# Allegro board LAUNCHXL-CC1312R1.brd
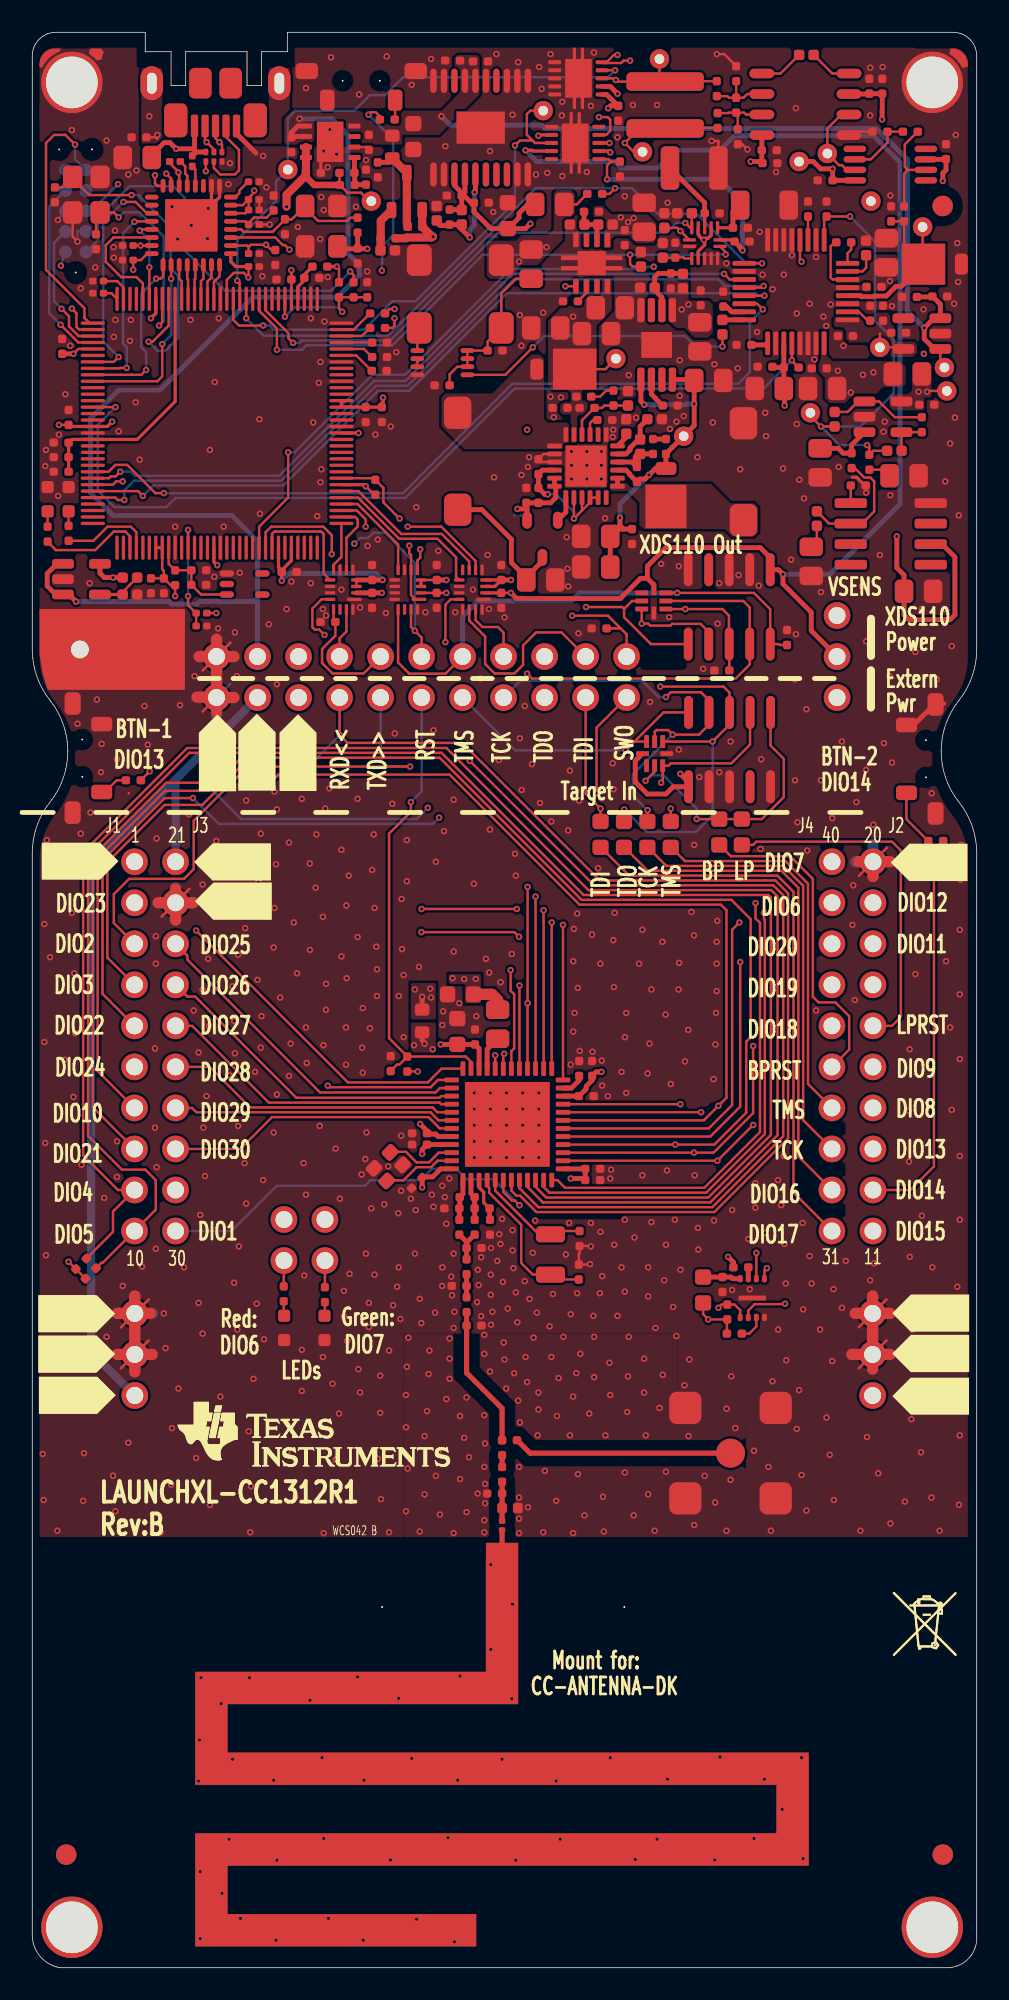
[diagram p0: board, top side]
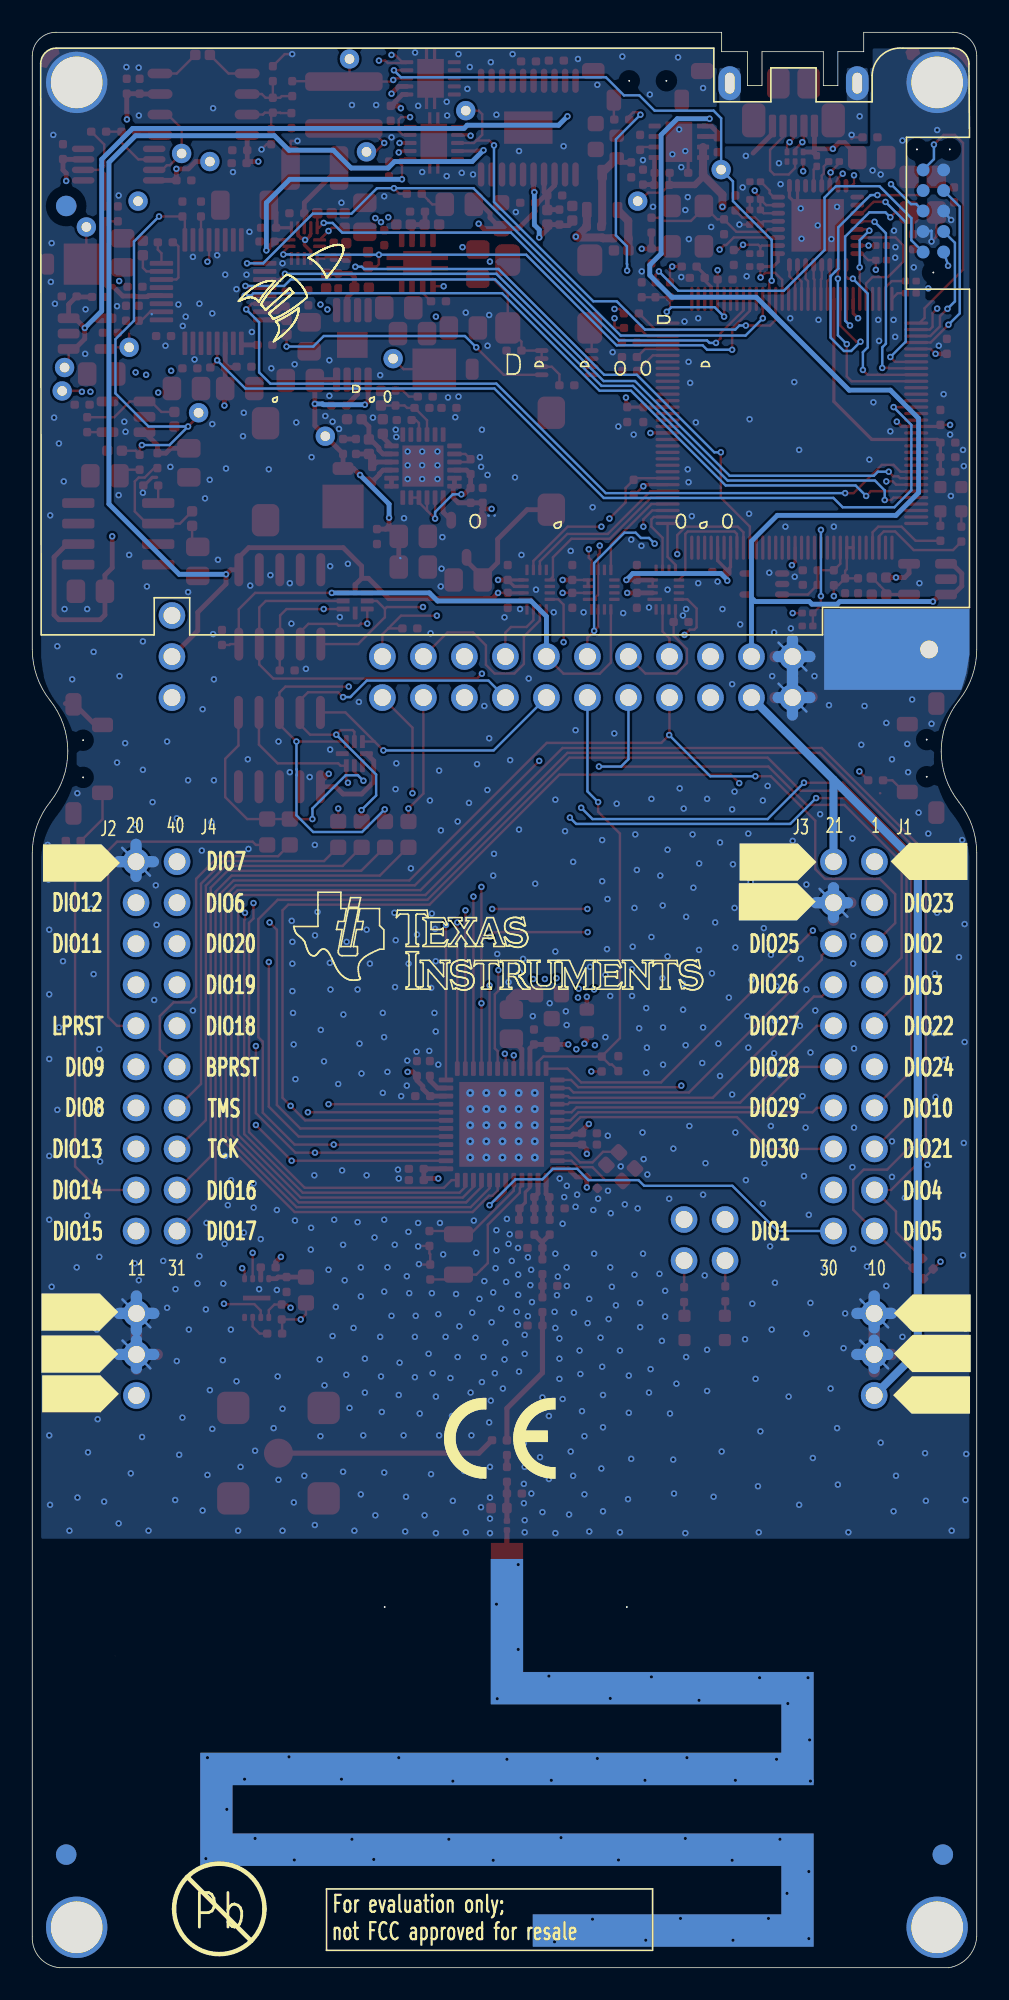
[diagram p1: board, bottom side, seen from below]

Outline 58.5 x 119.8 mm; copper layers: TOP, L2, L3, BOTTOM. Coordinates in mm from the lower left corner of the outline.
Outline path: 0,118.34 0,81.6 arc(0.28,79.93) 1.1,78.45 arc(1.92,76.97) 2.2,75.3 arc(1.92,73.63) 1.1,72.15 arc(0.28,70.67) 0,69 0,1.95 arc(0.51,0.67) 1.72,0 56.8,0 arc(58.05,0.63) 58.5,1.95 58.5,69 arc(58.22,70.67) 57.4,72.15 arc(56.58,73.63) 56.3,75.3 arc(56.58,76.97) 57.4,78.45 arc(58.22,79.93) 58.5,81.6 58.5,118.34 arc(58.07,119.37) 57.04,119.8 15.8,119.8 15.8,118.6 14.2,118.6 14.2,116.5 13.3,116.5 13.3,118.6 9.5,118.6 9.5,116.5 8.6,116.5 8.6,118.6 7,118.6 7,119.8 1.46,119.8 arc(0.43,119.37) 0,118.34

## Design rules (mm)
constraint set DEFAULT: min track width 0.15
nets with their own width: min track width 0.15; nets GND VDDR VDDS WMCU_VDD XDS_VCC

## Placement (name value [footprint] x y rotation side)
A1  868MHz/915MHz  [ANTENNA_DN024N]  29.1 25.8 180 top
C1  12pF  [CAPC1005X60B2N]  3.95 107.3 270 top
C2  10nF  [CAPC1005X60B2N]  15.45 86.4 0 top
C3  10nF  [CAPC1005X60B2N]  2.25 95.5 90 top
C4  10nF  [CAPC1005X60B2N]  1.85 99.9 90 top
C5  1uF  [CAPC1005X60B2N]  51.9 101.95 90 top
C6  100nF  [CAPC0603X35A2N]  13.4 105.3 0 top
C7  10nF  [CAPC1005X60B2N]  7.35 86 270 top
C8  0.1uF  [CAPC1005X60B2N]  9.85 86.5 0 top
C9  12pF  [CAPC1005X60B2N]  1.4 110.2 270 top
C11  3.6pF  [CAPC1005X60B2N]  26.45 47 180 top
C21  3.6pF  [CAPC1005X60B2N]  27.4 46.3 270 top
C30  0.1uF  [CAPC1005X60B2N]  42.75 42.75 270 top
C31  100pF  [CAPC1005X60B2N]  28.35 46.3 270 top
C33  2.7pF  [CAPC1005X60B2N]  26.9 44.55 0 top
C34  6.2pF  [CAPC1005X60B2N]  26.9 42.2 180 top
C35  3pF  [CAPC1005X60B2N]  26.9 39.75 0 top
C36  100pF  [CAPC1005X60B2N]  29.1 32.65 270 top
C37  100pF  [CAPC1005X60B2N]  29.1 32.65 0 top
C38  0.1uF  [CAPC1005X60B2N]  16.05 104.5 180 top
C39  0.1uF  [CAPC1005X60B2N]  20.65 96.6 270 top
C40  1uF  [CAPC1005X60B2N]  21.65 96.6 270 top
C41  12pF  [CAPC1005X60B2N]  33.85 42.6 90 top
C42  1uF  [CAPC1005X60B2N]  8.15 86 270 top
C43  0.1uF  [CAPC1005X60B2N]  2.25 94.4 180 top
C44  1uF  [CAPC1005X60B2N]  2.25 93.5 180 top
C45  2.2uF  [CAPC1005X60B2N]  2.25 92.6 180 top
C46  0.1uF  [CAPC1005X60B2N]  16.85 104.6 0 top
C47  15pF  [CAPC1005X60B2N]  19.05 110.35 0 top
C48  2.2uF  [CAPC1005X60B2N]  16.05 113.3 270 top
C49  2.2uF  [CAPC1005X60B2N]  16.95 111.1 0 top
C50  10nF  [CAPC1005X60B2N]  9.85 85.6 0 top
C51  15pF  [CAPC1005X60B2N]  33.9 45.6 270 top
C52  0.1uF  [CAPC1005X60B2N]  21.05 85.9 90 top
C53  0.1uF  [CAPC1005X60B2N]  21.05 85.1 270 top
C54  0.1uF  [CAPC1005X60B2N]  25.05 85.9 90 top
C55  0.1uF  [CAPC1005X60B2N]  25.05 85.1 270 top
C56  0.1uF  [CAPC1005X60B2N]  29.05 85.9 90 top
C57  0.1uF  [CAPC1005X60B2N]  29.05 85.1 270 top
C60  DNM_0402  [CAPC1005X60B2N]  43.6 115.75 270 top
C61  DNM_0402  [CAPC1005X60B2N]  43.7 113.8 270 top
C62  DNM_0402  [CAPC1005X60B2N]  43.6 117.7 270 top
C63  0.1uF  [CAPC1005X60B2N]  52.65 116 90 top
C64  0.1uF  [CAPC1005X60B2N]  46.11 112.5 180 top
C65  1uF  [CAPC1005X60B2N]  51.85 116 90 top
C66  1uF  [CAPC1005X60B2N]  46.15 111.7 180 top
C67  100pF  [CAPC1005X60B2N]  53.2 108.1 90 top
C68  0.1uF  [CAPC1005X60B2N]  56.6 111.95 90 top
C69  0.1uF  [CAPC1005X60B2N]  48.65 110.63 0 top
C70  10uF  [CAPC2012X150N]  54 85.2 0 top
C71  1uF  [CAPC1005X60B2N]  50.7 91.75 0 top
C72  10uF  [CAPC2012X150N]  48.25 87.95 270 top
C73  10uF  [CAPC2012X150N]  48.8 94.05 270 top
C74  2.2uF  [CAPC1005X60B2N]  55.1 95.05 90 top
C75  0.1uF  [CAPC1005X60B2N]  54.95 96.75 0 top
C76  47uF  [CAPC2012X150A2N]  53.1 92.35 0 top
C77  4.7uF  [CAPC2012X150A2N]  7.4 112.05 180 top
C78  100nF  [CAPC0603X35A2N]  6.25 105.7 180 top
C79  100nF  [CAPC0603X35A2N]  13.4 108.8 0 top
C80  100nF  [CAPC0603X35A2N]  13.39 109.45 0 top
C82  0.1uF  [CAPC1005X60B2N]  22.51 107.05 180 top
C83  100nF  [CAPC0603X35N]  13.4 106.1 0 top
C84  100nF  [CAPC0603X35N]  6.25 106.6 180 top
C85  4.7uF  [CAPC1005X60B2N]  15.05 105.4 90 top
C86  4.7uF  [CAPC1005X60B2N]  14.95 109.7 270 top
C87  100nF  [CAPC0603X35N]  13.4 107.9 0 top
C88  12pF  [CAPC1005X60B2N]  15.65 107.3 90 top
C89  12pF  [CAPC1005X60B2N]  20.15 105.5 90 top
C90  0.1uF  [CAPC1005X60B2N]  49.2 108.4 90 top
C92  1uF  [CAPC1005X60B2N]  48.05 108.4 90 top
C93  1uF  [CAPC1005X60B2N]  44.55 100.45 180 top
C94  1uF  [CAPC1005X60B2N]  50.83 101 180 top
C96  0.1uF  [CAPC1005X60B2N]  25.85 97.95 180 top
C97  0.1uF  [CAPC1005X60B2N]  45.85 99.1 180 top
C98  10uF  [CAPC2012X150N]  46.55 97.75 180 top
C99  0.1uF  [CAPC1005X60B2N]  49.2 99 180 top
C100  0.1uF  [CAPC1005X60B2N]  52.6 104.05 180 top
C101  10uF  [CAPC2012X150N]  49.85 97.75 180 top
C102  10uF  [CAPC2012X150N]  52.9 105.25 90 top
C103  0.1uF  [CAPC1005X60B2N]  55.75 103.45 0 top
C104  2.2uF  [CAPC1005X60B2N]  54.8 103.42 180 top
C105  0.1uF  [CAPC1005X60B2N]  53.2 101.2 0 top
C106  2.2uF  [CAPC1005X60B2N]  52.7 101.95 90 top
C107  4.7uF  [CAPC1005X60B2N]  30.6 91.6 270 top
C108  0.1uF  [CAPC1005X60B2N]  31.35 92.45 90 top
C109  4.7uF  [CAPC2012X150A2N]  32.4 85.9 180 top
C110  10nF  [CAPC1005X60B2N]  35 95.8 0 top
C111  4.7nF  [CAPC1005X60N]  36.79 94.95 90 top
C112  220nF  [CAPC1005X60A2N]  38.1 95.85 0 top
C113  7.5pF  [CAPC1005X60B2N]  38.45 93.7 90 top
C114  10uF  [CAPC2012X150A2N]  35.8 88.6 180 top
C115  10uF  [CAPC2012X150A2N]  32.7 101.5 180 top
C116  10uF  [CAPC2012X150A2N]  34.05 101.15 0 top
C117  10uF  [CAPC2012X150A2N]  35.8 86.7 180 top
C118  0.1uF  [CAPC1005X60B2N]  33.15 96.55 180 top
C119  0.1uF  [CAPC1005X60B2N]  37.15 89.05 270 top
C120  6.8pF  [CAPC1005X60B2N]  36 96.7 90 top
C121  0.1uF  [CAPC1005X60B2N]  27.3 118 0 top
C122  2.2uF  [CAPC1005X60B2N]  26.5 118.05 180 top
C123  2.2uF  [CAPC1005X60B2N]  26.6 109.7 180 top
C124  0.1uF  [CAPC1005X60B2N]  27.35 109.25 0 top
C125  22uF  [CAPC1608X100A2N]  29.45 107.65 90 top
C126  22pF  [CAPC1005X60B2N]  25.85 107.9 90 top
C127  10uF  [CAPC2012X150A2N]  34.9 102.75 0 top
C128  0.1uF  [CAPC1005X60B2N]  36.7 107.55 270 top
C130  10uF  [CAPC2012X150A2N]  37.9 107.45 90 top
C131  0.1uF  [CAPC1005X60B2N]  34.25 48.75 0 top
C132  12pF  [CAPC1005X60B2N]  34.25 49.45 0 top
C135  10nF  [CAPC1005X60B2N]  35.1 108.7 180 top
C136  10nF  [CAPC1005X60B2N]  39.55 103.95 90 top
C137  10nF  [CAPC1005X60B2N]  33.8 103.15 180 top
C138  10nF  [CAPC1005X60B2N]  39.05 96.7 0 top
C139  10uF  [CAPC2012X150A2N]  41.35 101.85 270 top
C140  0.1uF  [CAPC1005X60B2N]  41.4 102.9 90 top
C141  2.2uF  [CAPC1005X60B2N]  43.4 107.7 0 top
C142  2.2uF  [CAPC1005X60B2N]  41.65 108.6 0 top
C143  2.2uF  [CAPC1005X60B2N]  39.83 105.85 90 top
C144  0.1uF  [CAPC1005X60B2N]  43.5 106.85 0 top
C145  0.1uF  [CAPC1005X60B2N]  36.4 111.8 270 top
C146  0.1uF  [CAPC1005X60B2N]  36.3 115.25 270 top
C147  0.1uF  [CAPC1005X60B2N]  28.2 100.1 0 top
C149  3.3uF  [CAPC1608X90A2N]  23.6 112.55 90 top
C150  0.1uF  [CAPC1005X60B2N]  20.85 113.45 270 top
C151  10nF  [CAPC1005X60B2N]  21.4 111.75 270 top
C221  0.1uF  [CAPC1005X60B2N]  34.67 55.2 90 top
C222  12pF  [CAPC1005X60B2N]  33.85 53.95 0 top
C231  1uF  [CAPC1005X60B2N]  33.88 55.2 90 top
C232  10uF  [CAPC2012X150A2N]  41 98.25 0 top
C331  22uF  [CAPC1608X100A2N]  27.32 60.25 180 top
C341  22uF  [CAPC1608X100A2N]  26.32 57.15 90 top
C342  0.1uF  [CAPC1005X60B2N]  27.42 57.15 90 top
C351  0.1uF  [CAPC1005X60B2N]  22.2 55.5 90 top
C441  0.1uF  [CAPC1005X60B2N]  24.45 51.65 180 top
C451  0.1uF  [CAPC1005X60B2N]  24.45 50.95 180 top
C481  0.1uF  [CAPC1005X60B2N]  24.15 48.9 225 top
CR1  LPL296-J2L2-25  [LEDC1707X65L]  18.1 38.85 90 top
CR2  LS L296-P2Q2-1  [LEDC1708X67L]  15.6 38.85 90 top
CR4  LS L296-P2Q2-1  [LEDC1708X67L]  0.95 91.65 270 top
CR5  LPL296-J2L2-25  [LEDC1707X65L]  2.25 91.65 270 top
CR6  TPD4E004DRY  [SON50P100X145X60-6N]  10.75 111.8 0 top
CR7  TPD6E004RSER  [QFN50P150X150X60-8N]  37.75 85.1 270 top
CR8  TPD6E004RSER  [QFN50P150X150X60-8N]  38.05 74.4 0 top
CR9  MBRM120L  [DIO_MBRM120_A2N]  55.2 105.45 0 top
CR10  MBRM120L  [DIO_MBRM120_A2N]  33.6 98.95 180 top
CR11  MBRM120L  [DIO_MBRM120_A2N]  39.25 90.45 90 top
FIDU1  FIDU_1.27mm  [FID127X142]  56.39 109.05 0 top
FIDU2  FIDU_1.27mm  [FID127X142]  2.1 7 0 top
FIDU3  FIDU_1.27mm  [FID127X142]  56.4 7 0 top
FIDU4  FIDU_1.27mm  [FID127X142]  56.4 109.05 180 bottom
FIDU5  FIDU_1.27mm  [FID127X142]  2.1 7 180 bottom
FIDU6  FIDU_1.27mm  [FID127X142]  56.4 7 180 bottom
FL1  BLM18HE152SN1  [FIL_BLM18HE152SN1DL]  24.15 57.9 90 top
FL2  BLM18HE152SN1  [FIL_BLM18HE152SN1DL]  22.3 113.4 270 top
J1  SSQ-110-23-L-D  [SAMTEC_SSQ11023LD_A2B]  6.33 68.46 0 bottom
J2  SSQ-110-23-L-D  [SAMTEC_SSQ11023LD_A2B]  49.53 68.46 0 bottom
J6  105164-0001  [MOLEX_1051640001_A2N]  10.05 114 0 top
J7  SMA-10V21-TGG  [HUSTSAN_SMA10V21TGGAN]  43.25 31.85 0 top
L11  7.5nH  [INDC1005X60D2N]  26.45 46.3 270 top
L12  27nH  [INDC1005X60D2N]  27.4 47.7 180 top
L22  BLM21PG221SN1  [INDC2012X150N]  30.9 106.35 270 top
L23  BLM21PG221SN1  [INDC2012X150N]  31.15 109.15 0 top
L24  BLM21PG221SN1  [INDC2012X150N]  53.3 98.65 0 top
L25  4.7uH  [IND_7447789004N]  26.35 90.25 90 top
L26  4.7uH  [IND_7447789004N]  44.05 89.6 90 top
L32  7.5nH  [INDC1005X60D2N]  27.4 47 0 top
L33  6.8nH  [INDC1005X60D2N]  26.9 43.85 270 top
L34  6.8nH  [INDC1005X60D2N]  26.9 41.5 270 top
L331  6.8uH  [INDC2012X150A2N]  28.82 57.5 90 top
LBL1  NON_COMPONENT_LABEL_8mm  [LABEL_PB-FREE_8MM_A2N]  54.05 25.9 180 bottom
LBL2  TI_LOGO  [TI_LOGO_1]  10 35.03 0 top
LBL4  -  [LABEL_FOR_EVALUATION_ONLY]  40.12 1.22 180 bottom
LBL5  CE_label  [CE_LABEL]  30.38 30.28 180 bottom
LBL6  -  [TRASH]  53.38 19.3 0 top
M1  SNT-100-BK-G  [SAMTEC_SNT100BKG]  16.88 42.5 90 top
M2  SNT-100-BK-G  [SAMTEC_SNT100BKG]  19.38 42.5 90 top
M3  SNT-100-BK-G  [SAMTEC_SNT100BKG]  12.65 77.3 90 top
M4  SNT-100-BK-G  [SAMTEC_SNT100BKG]  15.25 77.3 90 top
M5  SNT-100-BK-G  [SAMTEC_SNT100BKG]  17.75 77.3 90 top
M6  SNT-100-BK-G  [SAMTEC_SNT100BKG]  20.25 77.3 90 top
M7  SNT-100-BK-G  [SAMTEC_SNT100BKG]  22.85 77.3 90 top
M8  SNT-100-BK-G  [SAMTEC_SNT100BKG]  25.35 77.3 90 top
M9  SNT-100-BK-G  [SAMTEC_SNT100BKG]  27.95 77.3 90 top
M10  SNT-100-BK-G  [SAMTEC_SNT100BKG]  30.45 77.3 90 top
M11  SNT-100-BK-G  [SAMTEC_SNT100BKG]  33.05 77.3 90 top
M12  SNT-100-BK-G  [SAMTEC_SNT100BKG]  35.55 77.3 90 top
M13  SNT-100-BK-G  [SAMTEC_SNT100BKG]  38.15 77.3 90 top
M14  SNT-100-BK-G  [SAMTEC_SNT100BKG]  51.15 79.9 90 top
MH1  RLCBSC-10-01  [MECH_RLCBSC1001_B2B]  2.45 2.5 180 bottom
MH2  RLCBSC-10-01  [MECH_RLCBSC1001_B2B]  55.75 2.5 180 bottom
MH3  RLCBSC-10-01  [MECH_RLCBSC1001_B2B]  2.45 116.7 180 bottom
MH4  RLCBSC-10-01  [MECH_RLCBSC1001_B2B]  55.75 116.7 180 bottom
MH5  HOLE_1.1mm_PTH  [MTG110_170]  2.95 81.6 0 top
NOREF  -  []  33.55 35.5 0 top
NOREF#2  -  []  -1.95 38.1 0 top
NOREF#3  -  []  51.45 66 0 top
NOREF#4  -  []  8.35 63.6 0 top
NOREF#5  -  []  -73.08 125.52 0 top
NOREF#6  -  []  -1.95 35.6 0 top
NOREF#7  -  []  -4.35 67.3 0 top
NOREF#8  -  []  -59.23 124.59 0 top
NOREF#9  -  []  51.55 38.1 0 top
NOREF#10  -  []  51.55 35.6 0 top
NOREF#11  -  []  56.3 75.34 0 top
NOREF#12  -  []  0.85 -28.78 0 top
NOREF#13  -  []  16.45 70.4 90 top
NOREF#14  -  []  58.03 0.61 0 top
NOREF#15  -  []  13.85 70.5 90 top
NOREF#16  -  []  52.06 0 90 top
NOREF#17  -  []  -70.48 81.55 0 top
NOREF#18  -  []  8.35 65.9 0 top
NOREF#19  #VALUE  [unnamed#2]  21.67 22.32 0 top
NOREF#20  -  []  -75.31 -10.05 90 top
NOREF#21  -  []  -178.4 -140.5 0 top
NOREF#22  -  []  53.05 34 0 top
NOREF#23  -  []  -2.05 32.9 0 top
NOREF#24  -  []  0 112.17 0 top
NOREF#25  -  []  17.65 67.9 90 top
NOREF#26  -  []  6.85 38.1 180 bottom
NOREF#27  -  []  5.55 67.1 180 bottom
NOREF#28  -  []  57.95 34.3 180 bottom
NOREF#29  -  []  60.15 66 180 bottom
NOREF#30  -  []  51.48 89.52 180 bottom
NOREF#31  -  []  60.25 35.6 180 bottom
NOREF#32  -  []  60.25 38.2 180 bottom
NOREF#33  -  []  6.85 32.9 180 bottom
NOREF#34  -  []  17.15 65.9 180 bottom
NOREF#35  -  []  6.85 35.6 180 bottom
NOREF#36  -  []  17.05 63.6 180 bottom
P1  BB02-HC031-KB1-603000  [GRADCONN_BB02HC031KB1603000_A2B]  52.05 35.42 90 top
P2  BB02-HC031-KB1-603000  [GRADCONN_BB02HC031KB1603000_A2B]  6.35 35.42 90 top
P4  BB02-HJ221-KB1-603000  [GRADCONN_BB02HJ221KB160300_A2B]  36.81 81.16 180 top
P5  FTSH-105-01-F-DV-K  [SAMTEC_FTSH-105-01-F-DV-K-10L]  40.65 73.1 0 top
P6  BB02-HJ041-KB1-603000  [GRADCONN_BB02HJ041KB1603000_A2B]  15.59 43.77 0 top
P7  FTSH-105-01-F-DV-K  [SAMTEC_FTSH-105-01-F-DV-K-10L]  45.71 86.53 180 top
P8  TC2050-IDC-NL  [TAGCONNECT_TC2050IDCNL_A2N]  2.05 106.2 90 bottom
P10  BB02-HC031-KB1-603000  [GRADCONN_BB02HC031KB1603000_A2B]  49.85 83.7 270 top
Q1  NX2301P  [SOT95P230X110-3N]  22.25 108.8 0 top
Q2  Si2323DS  [SOT95P237X130-3N]  32.55 89.6 180 top
R2  DNM  [RESC1005X40B2N]  3.35 43.9 225 top
R3  DNM  [RESC1005X40B2N]  3.95 43.3 225 top
R11  2.2k  [RESC1005X40B2N]  43.05 41.05 270 top
R14  220  [RESC1005X40B2N]  15.57 41.25 90 top
R15  180  [RESC1005X40B2N]  18.12 41.2 90 top
R17  10k  [RESC1005X40B2N]  19 103.4 90 top
R18  4.7k  [RESC1005X40B2N]  8.85 86.5 270 top
R20  100  [RESC1005X40B2N]  19.9 103.4 90 top
R21  DNM  [RESC1005X40B2N]  20.75 103.4 90 top
R23  180  [RESC1005X40B2N]  0.95 89.2 270 top
R25  220  [RESC1005X40B2N]  2.25 89.25 270 top
R27  1k  [RESC1005X40B2N]  21.85 101.5 180 top
R28  4.87k  [RESC1005X40B2N]  21.95 98.85 180 top
R29  1k  [RESC1005X40B2N]  21.05 100.6 0 top
R30  1k  [RESC1005X40B2N]  21.05 99.7 0 top
R31  51  [RESC1005X40B2N]  17.35 105.3 0 top
R32  33k  [RESC1005X40B2N]  6.15 113.3 0 top
R33  51k  [RESC1005X40B2N]  19.95 111.1 180 top
R34  30k  [RESC1005X40B2N]  20.67 111.3 270 top
R39  1k  [RESC1005X40B2N]  21.85 102.4 180 top
R46  DNM  [RESC1608X55N]  39.55 69.35 90 top
R47  DNM  [RESC1608X55N]  38.1 69.35 90 top
R48  0  [RESC1608X55A2N]  36.65 69.35 90 top
R49  0  [RESC1608X55A2N]  35.2 69.35 90 top
R51  0  [RESC1608X55N]  43.95 69.5 90 top
R52  DNM  [RESC1608X55N]  42.55 69.5 90 top
R55  100  [RESC1005X40B2N]  55.5 69.75 0 top
R56  100  [RESC1005X40B2N]  5.8 73.5 0 top
R57  100  [RESC1005X40B2N]  22.45 114.4 180 top
R58  3.3k  [RESC1005X40B2N]  21.25 92.1 270 top
R59  DNM  [RESC1005X40B2N]  43.95 39.25 180 top
R60  DNM  [RESC1005X40B2N]  44.35 43.35 180 top
R61  100k  [RESC1005X40B2N]  17.85 83.3 0 top
R62  100k  [RESC1005X40B2N]  34.65 82.9 0 top
R63  100k  [RESC1005X40B2N]  42.25 80.3 0 top
R65  100k  [RESC1005X40B2N]  46.75 82.8 270 top
R69  0  [RESC1005X40B2N]  42.4 115.85 90 top
R70  0  [RESC1005X40B2N]  42.45 114.8 270 top
R71  2.61k  [RESC1005X40N]  48.4 118.4 180 top
R72  220  [RESC1005X40B2N]  54 108.1 90 top
R73  0  [RESC1005X40B2N]  54.85 113.65 180 top
R74  DNM  [RESC1005X40B2N]  52.05 113.65 0 top
R76  1  [RESC3246X70A2N]  39.2 116.75 270 top
R77  0.22  [RESC1005X50A2N]  48.6 89.25 90 top
R78  10k  [RESC1005X40B2N]  50.75 93.75 270 top
R79  1k  [RESC1005X40A2N]  52.95 93.9 0 top
R80  0.22  [RESC1005X50A2N]  49.7 95.4 90 top
R81  0  [RESC1005X40B2N]  51.85 93.65 270 top
R82  10k  [RESC0603X35N]  9.91 111.5 90 top
R83  10k  [RESC0603X35N]  8.51 111.8 0 top
R84  12k  [RESC0603X35N]  14.05 110.55 180 top
R85  510k  [RESC1005X40N]  22.47 106.3 180 top
R86  DNM  [RESC1005X40B2N]  23.25 107.75 0 top
R87  1Meg  [RESC1005X40B2N]  20.15 107.4 90 top
R92  60.4k  [RESC1005X40N]  51.65 106.9 270 top
R93  100k  [RESC1005X40B2N]  49.8 106.8 0 top
R94  100k  [RESC1005X40B2N]  42.8 103.75 270 top
R96  100  [RESC1005X40B2N]  31.35 91.6 270 top
R97  1Meg  [RESC1005X40B2N]  33.9 96.55 0 top
R98  1Meg  [RESC1005X40B2N]  37.45 92.9 270 top
R99  86.6k  [RESC1005X40N]  37.65 93.7 90 top
R100  10k  [RESC1005X40B2N]  39.25 93.7 90 top
R101  95.3k  [RESC1005X40N]  36.9 97.6 270 top
R102  10k  [RESC1005X40B2N]  33.7 97.25 0 top
R103  53.6k  [RESC1005X40N]  26.6 108.8 270 top
R104  30.1k  [RESC1005X40N]  25.05 108.15 90 top
R106  100k  [RESC1005X40B2N]  35.3 109.8 180 top
R110  100k  [RESC1005X40B2N]  46.55 99.05 0 top
R113  1k  [RESC0603X35N]  3.75 103.65 0 top
R114  1k  [RESC0603X35N]  3.75 104.4 0 top
R115  10k  [RESC0603X35N]  10.15 83.85 0 top
R116  20k  [RESC0603X35N]  10.15 83.05 0 top
R117  453k  [RESC1005X40N]  35.05 107.9 0 top
R118  49.9k  [RESC1005X40N]  33.3 107.9 0 top
R119  93.1k  [RESC1005X40N]  40.3 104.85 270 top
R120  10k  [RESC1005X40A2N]  37.65 104 0 top
R124  82  [RESC3216X75N]  46.85 109.1 180 top
R125  36.5  [RESC3225X75N]  42.5 111.4 180 top
R126  47k  [RESC1005X40N]  37.7 105.3 90 top
R127  47k  [RESC1005X40N]  40.85 108.6 180 top
R128  2.2k  [RESC1005X40A2N]  39.05 105.85 90 top
R129  47k  [RESC1005X40N]  39.15 107.7 90 top
R131  22  [RESC1005X40N]  42.75 101.1 90 top
R133  0  [RESC1608X55N]  41.55 42.75 270 top
R136  57.6k  [RESC1005X40A2N]  5.6 86.05 0 top
R137  27k  [RESC1005X40A2N]  6.5 85 180 top
R351  100k  [RESC1005X40B2N]  23.22 56.4 270 top
SW1  1188E-1K2-V  [SW_1188E1K2V_A2N]  2.5 78.25 270 top
SW2  1188E-1K2-V  [SW_1188E1K2V_A2N]  55.95 71.45 90 top
SW3  1188E-1K2-V  [SW_1188E1K2V_A2N]  23.75 117.4 180 top
TP1  HOLE_0.6mm_PTH  [MTG60_120]  56.65 97.6 0 top
TP2  HOLE_0.6mm_PTH  [MTG60_120]  47.5 111.8 0 top
TP3  HOLE_0.6mm_PTH  [MTG60_120]  40.35 94.8 0 top
TP4  HOLE_0.6mm_PTH  [MTG60_120]  51.95 109.35 0 top
TP5  HOLE_0.6mm_PTH  [MTG60_120]  36.15 99.6 0 top
TP6  HOLE_0.6mm_PTH  [MTG60_120]  52.5 100.3 0 top
TP7  HOLE_0.6mm_PTH  [MTG60_120]  55.15 107.75 0 top
TP8  HOLE_0.6mm_PTH  [MTG60_120]  48.2 96.25 0 top
TP9  HOLE_0.6mm_PTH  [MTG60_120]  49.25 112.3 0 top
TP10  HOLE_0.6mm_PTH  [MTG60_120]  56.5 99.05 0 top
TP11  HOLE_0.6mm_PTH  [MTG60_120]  21 109.35 0 top
TP12  HOLE_0.6mm_PTH  [MTG60_120]  37.8 112.4 0 top
TP13  HOLE_0.6mm_PTH  [MTG60_120]  38.85 118.15 0 top
TP14  HOLE_0.6mm_PTH  [MTG60_120]  31.65 114.95 0 top
TP15  HOLE_0.6mm_PTH  [MTG60_120]  15.83 111.3 0 top
U1  CC1312R1F3RGZ  [QFNFC50P700X700X100-49A2N]  26.67 48.75 0 top
U4  MX25R8035FZUIL0  [SON50P300X200X60-9B2L]  43.85 40.25 0 top
U5  TM4C1294NCPDTT3R  [QFP40P1600X1600X120-128N]  5.25 87.9 0 top
U6  LM4040B25IDCK  [SOT65P210X110-5N]  12.05 86.3 270 top
U7  TPS79601DR  [SON65P300X300X100-9AL]  16.95 114 270 top
U8  SN74AVC4T245RSV  [QFNFC40P180X260X55-16A2L]  19.95 84.7 90 top
U9  SN74AVC4T245RSV  [QFNFC40P180X260X55-16A2L]  27.95 84.7 90 top
U10  SN74AVC4T245RSV  [QFNFC40P180X260X55-16A2L]  23.95 84.7 90 top
U11  OPA320AIDBV  [SOT95P280X145-5A2N]  51.55 96.95 270 top
U12  INA118U  [SOIC127P600X175-8N]  45.19 117.25 270 top
U13  OPA211AIDGKT  [SOP65P490X110-8N]  50.95 112.58 270 top
U14  REF5025AID  [SOIC127P600X175-8A2N]  55.65 86.85 90 top
U15  USB3300-EZK  [QFNWB50P500X500X100-33N]  11.6 110.3 180 top
U16  ADS127L01IPBS  [QFP50P700X700X120-32A2N]  50.5 102 90 top
U17  SN74LVC2G74DCU  [SOP50P310X90-8N]  23.85 100.1 270 top
U18  LP5907MFX-1.8  [SOT95P280X145-5A2N]  56.25 100.2 90 top
U19  TPS65130RGE  [QFNFC50P400X400X100-25D2N]  32.35 94.2 270 top
U20  TPS76801QPWP  [TSSOP65P640X120-21N]  30.7 116.8 180 top
U21  TPS7A4901DRB  [SON65P300X300X100-9A2N]  35.62 106.95 180 top
U22  TPS7A3001MDGNTEP  [SOP65P490X110-9B2N]  39.65 102.6 180 top
U24  TS3A4751RUCR  [QFNFC40P200X200X40-14A2N]  42.45 107.7 180 top
U25  TS3A24159DRC  [SON50P300X300X100-11A2N]  35.1 111.95 90 top
U26  TS3A24159DRC  [SON50P300X300X100-11A2N]  35.3 115.95 90 top
U27  TPS73101DBV  [SOT95P280X145-5A2N]  1.9 86.9 270 top
Y1  32.768kHz  [XTAL_FC-135N]  32.1 42.9 90 top
Y2  48MHz  [OSCCC200X160X45-4A2N]  21.95 48.7 45 top
Y3  16MHz  [OSCCC250X320X100-4BN]  2.5 110.85 270 top
Y4  24MHz  [OSCCC250X320X70-4AN]  16.9 109.05 270 top
Y5  16.384MHz  [OSCSC508P500X700X180-4N]  29.05 105.7 180 top
Z60  3.3nH  [INDC1005X60B2N]  29.1 31 270 top
Z61  DNM  [CAPC1005X60B2N]  29.1 29.35 180 top
Z62  DNM  [IND_LQW15AN]  29.1 28.45 0 top
Z63  5.6pF  [CAPC0603X35B2N]  29.1 27.65 270 top

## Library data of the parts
A1 = ANTENNA_PCB_0: User Part Number: #PN
C1-C5 C7-C9 C11 C21 C30 C31 C33-C57 C60-C69 C71 C74 C75 C82 C85 C86 C88-C90 C92-C94 C96 C97 C99 C100 C103-C108 C110 C113 C118-C124 C126 C128 C131 C132 C135-C138 C140-C147 C150 C151 C221 C222 C231 C342 C351 C441 C451 C481 Z61 = CAPACITOR: User Part Number: #PN
C6 C78-C80 = CAPACITOR: User Part Number: #PN; alternate symbols: (CAPC0603X35A2L,CAPC0603X35A2M)
C70 C72 C73 C98 C101 C102 = CAPACITOR: User Part Number: #PN; alternate symbols: (CAPC2012X150L,CAPC2012X150M)
C76 C77 C109 C114-C117 C127 C130 C139 C232 = CAPACITOR: User Part Number: #PN; alternate symbols: (CAPC2012X150A2L,CAPC2012X150A2M)
C83 C84 C87 = CAPACITOR: alternate symbols: (CAPC0603X35L,CAPC0603X35M)
C111 = CAPACITOR: User Part Number: #PN; alternate symbols: (CAPC1005X60L,CAPC1005X60M)
C112 = CAPACITOR: User Part Number: #PN; alternate symbols: (CAPC1005X60A2L,CAPC1005X60A2M)
C125 C331 C341 = CAPACITOR: User Part Number: #PN; alternate symbols: (CAPC1608X100A2L,CAPC1608X100A2M)
C149 = CAPACITOR: User Part Number: #PN; alternate symbols: (CAPC1608X90A2L,CAPC1608X90A2M)
CR1 CR5 = LED_0: alternate symbols: (LEDC1707X65L,LEDC1707X65M)
CR2 CR4 = LED_0: alternate symbols: (LEDC1708X67L,LEDC1708X67M)
CR6 = DIODE_TPD4E004_SON6: User Part Number: #PN; alternate symbols: (SON50P100X145X65-6L,SON50P100X145X65-6M)
CR7 CR8 = DIODE_TVS_TPD6E004_QFN8_V1: alternate symbols: (QFN50P150X150X60-8L,QFN50P150X150X60-8M)
CR9-CR11 = DIODE_SCH_0: alternate symbols: (DIO_MBRM120_A2L,DIO_MBRM120_A2M)
FIDU1-FIDU6 = FIDMARK
FL1 FL2 = FILTER_2PIN: alternate symbols: (FIL_BLM18HE152SN1DL,FIL_BLM18HE152SN1DM)
J1 J2 = CONN_HEADER_2X10_J_S_V1: User Part Number: #PN; alternate symbols: (SAMTEC_SSQ11023LD_A2C,SAMTEC_SSQ11023LD_A2A)
J6 = CONN_USB_MICRO_B_2MH: User Part Number: #PN; alternate symbols: (MOLEX_1051640001_A2L,MOLEX_1051640001_A2M)
J7 = CONN_COAX_1_4: alternate symbols: (HUSTSAN_SMA10V21TGGL,HUSTSAN_SMA10V21TGGM)
L11 L32-L34 = INDUCTOR_HOR_1_1: User Part Number: #PN
L12 = INDUCTOR_HOR_1_0: User Part Number: #PN
L22-L24 = INDUCTOR: alternate symbols: (INDC2012X150L,INDC2012X150M)
L25 L26 = IND_HOR_0: alternate symbols: (IND_7447789004L,IND_7447789004M)
L331 = INDUCTOR: User Part Number: #PN; alternate symbols: (INDC2012X150A2L,INDC2012X150A2M)
LBL1 = LABEL_Pb-free_V1: User Part Number: #PN
LBL2 = TI_LOGO_V1
LBL4 = LABEL_FOR_EVALUATOIN_ONLY: User Part Number: #PN
LBL5 = CE_LABEL
LBL6 = TRASH_V1
M1-M14 = MECH_SHUNT_JUMPER_V1: User Part Number: #PN
MH1-MH4 = MECH_SUPPORT_SCREW_FASTENED_V1: User Part Number: #PN
MH5 TP1-TP15 = HOLE_PTH
NOREF#19 = -: User Part Number: #PN
P1 P2 P10 = CONN_HEADER_3_P_S: User Part Number: #PN; alternate symbols: (GRADCONN_BB02HC031KB1603000_A2C,GRADCONN_BB02HC031KB1603000_A2A)
P4 = CONN_HEADER_2X11_P_S: User Part Number: #PN; alternate symbols: (GRADCONN_BB02HJ221KB160300_A2C,GRADCONN_BB02HJ221KB160300_A2A)
P5 P7 = CONN_HEADER_2X5: alternate symbols: (SAMTEC_FTSH-105-01-F-DV-K-10L,SAMTEC_FTSH-105-01-F-DV-K-10M)
P6 = CONN_HEADER_2X2_P: User Part Number: #PN; alternate symbols: (GRADCONN_BB02HJ041KB1603000_A2C,GRADCONN_BB02HJ041KB1603000_A2A)
P8 = CONN_IDC_TC2050-IDC-NL: User Part Number: #PN; alternate symbols: (TAGCONNECT_TC2050IDCNL_A2L,TAGCONNECT_TC2050IDCNL_A2M)
Q1 = MOSFET_P_NX2301P_SOT23-3: User Part Number: #PN; alternate symbols: (SOT95P230X110-3L,SOT95P230X110-3M)
Q2 = MOSFET_P_SI2323DS_SOT23-3: alternate symbols: (SOT95P237X130-3L,SOT95P237X130-3M)
R2 R3 R11 R14 R15 R17 R18 R20 R21 R23 R25 R27-R34 R39 R55-R60 R69 R70 R72-R74 R78 R81 R86 R87 R93 R94 R96-R98 R100 R102 R106 R351 = RESISTOR: User Part Number: #PN
R46 R47 R51 R52 R133 = RESISTOR: alternate symbols: (RESC1608X55L,RESC1608X55M)
R48 R49 = RESISTOR: User Part Number: #PN; alternate symbols: (RESC1608X55A2L,RESC1608X55A2M)
R61-R63 R65 R110 = RESISTOR: User Part Number: #PN; alternate symbols: (RESC1005X40B2L,RESC1005X40B2M)
R71 R85 R92 R99 R101 R103 R104 R117-R119 R126 R127 R129 R131 = RESISTOR: User Part Number: #PN; alternate symbols: (RESC1005X40L,RESC1005X40M)
R76 = RESISTOR: User Part Number: #PN; alternate symbols: (RESC3246X70A2L,RESC3246X70A2M)
R77 R80 = RESISTOR: User Part Number: #PN; alternate symbols: (RESC1005X50A2L,RESC1005X50A2M)
R79 R120 R128 R136 R137 = RESISTOR: alternate symbols: (RESC1005X40A2L,RESC1005X40A2M)
R82-R84 R113-R116 = RESISTOR: alternate symbols: (RESC0603X35L,RESC0603X35M)
R124 = RESISTOR: alternate symbols: (RESC3216X75L,RESC3216X75M)
R125 = RESISTOR: alternate symbols: (RESC3225X75L,RESC3225X75M)
SW1-SW3 = SWITCH_TACT_V2: alternate symbols: (SW_1188E1K2V_A2L,SW_1188E1K2V_A2M)
U1 = IC_RF_CC1312R1F3_VQFN48: User Part Number: #PN; alternate symbols: (QFNFC50P700X700X100-49A2L,QFNFC50P700X700X100-49A2M)
U4 = IC_FLASH_MX25R8035F_USON8: User Part Number: #PN; alternate symbols: (SON50P300X200X60-9B2L,SON50P300X200X60-9B2M)
U5 = IC_PROC_TM4C1294NCPDT_TQFP128: alternate symbols: (QFP40P1600X1600X120-128L,QFP40P1600X1600X120-128M)
U6 = IC_REF_LM4040_SC70-5: alternate symbols: (SOT65P210X110-5L,SOT65P210X110-5M)
U7 = IC_PM_TPS79601_SON8: alternate symbols: (SON65P300X300X100-9AL,SON65P300X300X100-9AM)
U8-U10 = IC_XCVR_SN74AVC4T245_UQFN16_2: User Part Number: #PN; alternate symbols: (QFNFC40P180X260X55-16A2L,QFNFC40P180X260X55-16A2M)
U11 = IC_OPAMP_OPA320_SOT23-5: User Part Number: #PN; alternate symbols: (SOT95P280X145-5A2L,SOT95P280X145-5A2M)
U12 = IC_OPAMP_INA118U_SO8: alternate symbols: (SOIC127P600X175-8L,SOIC127P600X175-8M)
U13 = IC_OPAMP_OPA211_MSOP8: alternate symbols: (SOP65P490X110-8L,SOP65P490X110-8M)
U14 = IC_REF_REF5025_SO8: User Part Number: #PN; alternate symbols: (SOIC127P600X175-8A2L,SOIC127P600X175-8A2M)
U15 = IC_PROC_USB3300_QFN32: alternate symbols: (QFNWB50P500X500X100-33L,QFNWB50P500X500X100-33M,QFNWB50P500X500X100-33DL,QFNWB50P500X500X100-33DM)
U16 = IC_ADC_ADS127L01_QFP32: User Part Number: #PN; alternate symbols: (QFP50P700X700X120-32A2L,QFP50P700X700X120-32A2M)
U17 = IC_LOGIC_SN74LVC2G74_VSSOP8: alternate symbols: (SOP50P310X90-8L,SOP50P310X90-8M)
U18 = IC_PM_LP5907-1_8_SOT23-5: User Part Number: #PN; alternate symbols: (SOT95P280X145-5A2L,SOT95P280X145-5A2M)
U19 = IC_PM_TPS65130_QFN24: User Part Number: #PN; alternate symbols: (QFNFC50P400X400X100-25D2L,QFNFC50P400X400X100-25D2M)
U20 = IC_PM_TPS76801Q_HTSSOP20: alternate symbols: (TSSOP65P640X120-21L,TSSOP65P640X120-21M)
U21 = IC_PM_TPS7A4901_SON8: User Part Number: #PN; alternate symbols: (SON65P300X300X100-9A2L,SON65P300X300X100-9A2M)
U22 = IC_PM_TPS7A3001_MSOP8: User Part Number: #PN; alternate symbols: (SOP65P490X110-9B2L,SOP65P490X110-9B2M)
U24 = IC_SWITCH_TS3A4751_QFN14: User Part Number: #PN; alternate symbols: (QFNFC40P200X200X40-14A2L,QFNFC40P200X200X40-14A2M)
U25 U26 = IC_SWITCH_TS3A24159_SON10: User Part Number: #PN; alternate symbols: (SON50P300X300X100-11A2L,SON50P300X300X100-11A2M)
U27 = IC_PM_TPS73101_SOT23-5: User Part Number: #PN; alternate symbols: (SOT95P280X145-5A2L,SOT95P280X145-5A2M)
Y1 = CRYSTAL: alternate symbols: (XTAL_FC-135L,XTAL_FC-135M)
Y2 = XTAL_4PINS_1_3: User Part Number: #PN; alternate symbols: (OSCCC200X160X45-4A2L,OSCCC200X160X45-4A2M)
Y3 = XTAL_4: alternate symbols: (OSCCC250X320X100-4BL,OSCCC250X320X100-4BM)
Y4 = XTAL_4: alternate symbols: (OSCCC250X320X70-4AL,OSCCC250X320X70-4AM)
Y5 = XTAL_GEN_EN: alternate symbols: (OSCSC508P500X700X180-4L,OSCSC508P500X700X180-4M)
Z60 = INDUCTOR: User Part Number: #PN
Z62 = INDUCTOR: alternate symbols: (IND_LQW15AL,IND_LQW15AM)
Z63 = CAPACITOR: User Part Number: #PN; alternate symbols: (CAPC0603X35B2L,CAPC0603X35B2M)

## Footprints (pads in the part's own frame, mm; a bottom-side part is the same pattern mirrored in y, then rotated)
ANTENNA_DN024N
  rect 2x1 smd: 1(0,0)
CAPC0603X35A2N
  custom 0.105x0.105 smd: 1(0,0) 2(0.66,0)
CAPC0603X35B2N
  custom 0.087x0.087 smd: 1(0,0) 2(0.56,0)
CAPC0603X35N
  custom 0.105x0.105 smd: 1(0,0) 2(0.66,0)
CAPC1005X60A2N
  custom 0.16x0.16 smd: 1(0,0) 2(0.9,0)
CAPC1005X60B2N
  custom 0.125x0.125 smd: 1(0,0) 2(0.924,0)
CAPC1005X60N
  custom 0.16x0.16 smd: 1(0,0) 2(0.9,0)
CAPC1608X90A2N
  custom 0.237x0.237 smd: 1(0,0) 2(1.6,0)
CAPC1608X100A2N
  custom 0.237x0.237 smd: 1(0,0) 2(1.6,0)
CAPC2012X150A2N
  custom 0.287x0.287 smd: 1(0,0) 2(1.8,0)
CAPC2012X150N
  custom 0.287x0.287 smd: 1(0,0) 2(1.8,0)
CE_LABEL
  oval 0.025x0.051 smd: 1(-0.15,0.1)
DIO_MBRM120_A2N
  rect 2.7x2.55 smd: 1(0,0)
  custom 0.2x0.2 smd: 2(2.35,0)
FID127X142
  round 1.27 smd: 1(0,0)
FIL_BLM18HE152SN1DL
  custom 0.188x0.188 smd: 1(0,0) 2(1.4,0)
GRADCONN_BB02HC031KB1603000_A2B
  round 1.65 hole 1.05: 1(0,0) 2(2.54,0) 3(5.08,0)
GRADCONN_BB02HJ041KB1603000_A2B
  round 1.65 hole 1.05: 1(0,0) 2(0,2.54) 3(2.54,0) 4(2.54,2.54)
GRADCONN_BB02HJ221KB160300_A2B
  round 1.65 hole 1.05: 1(0,0) 2(0,2.54) 3(2.54,0) 4(2.54,2.54) 5(5.08,0) 6(5.08,2.54) 7(7.62,0) 8(7.62,2.54) 9(10.16,0) 10(10.16,2.54) 11(12.7,0) 12(12.7,2.54) 13(15.24,0) 14(15.24,2.54) 15(17.78,0) 16(17.78,2.54) 17(20.32,0) 18(20.32,2.54) 19(22.86,0) 20(22.86,2.54) 21(25.4,0) 22(25.4,2.54)
HUSTSAN_SMA10V21TGGAN
  round 1.8 smd: 1(0,0)
  custom 0.5x0.5 smd: 2(-2.8,-2.8) 3(2.8,-2.8) 4(2.8,2.8) 5(-2.8,2.8)
IND_7447789004N
  custom 0.425x0.425 smd: 1(0,0) 2(6,0)
IND_LQW15AN
  custom 0.15x0.15 smd: 1(0,0) 2(0.98,0)
INDC1005X60B2N
  custom 0.125x0.125 smd: 1(0,0) 2(0.924,0)
INDC1005X60D2N
  custom 0.125x0.125 smd: 1(0,0) 2(0.924,0)
INDC2012X150A2N
  custom 0.287x0.287 smd: 1(0,0) 2(1.8,0)
INDC2012X150N
  custom 0.287x0.287 smd: 1(0,0) 2(1.8,0)
LEDC1707X65L
  custom 0.188x0.188 smd: 1(0,0) 2(1.501,0)
LEDC1708X67L
  custom 0.188x0.188 smd: 1(0,0) 2(1.501,0)
MECH_RLCBSC1001_B2B
  round 3.8 hole 3.2: 1(0,0)
MOLEX_1051640001_A2N
  custom 0.362x0.362 smd: (-1.162,0.35) (3.762,0.35)
  custom 0.35x0.35 smd: (0.362,2.65) (2.238,2.65)
  custom 0.113x0.113 smd: 1(0,0) 2(0.65,0) 3(1.3,0) 4(1.95,0) 5(2.6,0)
  oval 1.4x2.1 hole 0.6x1.3: M1(-2.65,2.65) M2(5.25,2.65)
MTG60_120
  round 1.2 hole 0.6: 1(0,0)
MTG110_170
  round 1.699 hole 1.1: 1(0,0)
OSCCC200X160X45-4A2N
  custom 0.2x0.2 smd: 1(0,0) 2(1.4,0) 3(1.4,1.1) 4(0,1.1)
OSCCC250X320X70-4AN
  custom 0.287x0.287 smd: 1(0,0) 2(2.5,0) 3(2.5,2) 4(0,2)
OSCCC250X320X100-4BN
  custom 0.299x0.299 smd: 1(0,0) 2(2.2,0) 3(2.2,1.699) 4(0,1.699)
OSCSC508P500X700X180-4N
  custom 0.388x0.388 smd: 1(0,0) 2(5.08,0) 3(5.08,4.2) 4(0,4.2)
QFN50P150X150X60-8N
  custom 0.075x0.075 smd: 1(0,0) 2(0.5,0) 3(1,0) 4(1.25,0.75) 5(1,1.5) 6(0.5,1.5) 7(0,1.5) 8(-0.25,0.75)
QFNFC40P180X260X55-16A2L
  custom 0.05x0.05 smd: 1(0,0) 2(0.4,-0.125) 3(0.8,-0.125) 4(1.2,-0.125) 5(1.825,0.09) 6(1.825,0.49) 7(1.825,0.89) 8(1.825,1.29) 9(1.2,1.505) 10(0.8,1.505) 11(0.4,1.505) 12(0,1.505) 13(-0.625,1.29) 14(-0.625,0.89) 15(-0.625,0.49) 16(-0.625,0.09)
QFNFC40P200X200X40-14A2N
  custom 0.05x0.05 smd: 1(0,0) 2(0.4,0) 3(0.8,0) 4(1.2,0) 5(1.6,0) 6(1.75,0.75) 7(1.75,1.15) 8(1.6,1.9) 9(1.2,1.9) 10(0.8,1.9) 11(0.4,1.9) 12(0,1.9) 13(-0.15,1.15) 14(-0.15,0.75)
QFNFC50P400X400X100-25D2N
  custom 0.075x0.075 smd: 1(0,0) 2(0.5,0) 3(1,0) 4(1.5,0) 5(2,0) 6(2.5,0) 7(3.2,0.7) 8(3.2,1.2) 9(3.2,1.7) 10(3.2,2.2) 11(3.2,2.7) 12(3.2,3.2) 13(2.5,3.9) 14(2,3.9) 15(1.5,3.9) 16(1,3.9) 17(0.5,3.9) 18(0,3.9) 19(-0.7,3.2) 20(-0.7,2.7) 21(-0.7,2.2) 22(-0.7,1.7) 23(-0.7,1.2) 24(-0.7,0.7)
  rect 2.55x2.55 smd: 25(1.25,1.95)
QFNFC50P700X700X100-49A2N
  custom 0.075x0.075 smd: 1(0,0) 2(0.5,0) 3(1,0) 4(1.5,0) 5(2,0) 6(2.5,0) 7(3,0) 8(3.5,0) 9(4,0) 10(4.5,0) 11(5,0) 12(5.5,0) 13(6.2,0.7) 14(6.2,1.2) 15(6.2,1.7) 16(6.2,2.2) 17(6.2,2.7) 18(6.2,3.2) 19(6.2,3.7) 20(6.2,4.2) 21(6.2,4.7) 22(6.2,5.2) 23(6.2,5.7) 24(6.2,6.2) 25(5.5,6.9) 26(5,6.9) 27(4.5,6.9) 28(4,6.9) 29(3.5,6.9) 30(3,6.9) 31(2.5,6.9) 32(2,6.9) 33(1.5,6.9) 34(1,6.9) 35(0.5,6.9) 36(0,6.9) 37(-0.7,6.2) 38(-0.7,5.7) 39(-0.7,5.2) 40(-0.7,4.7) 41(-0.7,4.2) 42(-0.7,3.7) 43(-0.7,3.2) 44(-0.7,2.7) 45(-0.7,2.2) 46(-0.7,1.7) 47(-0.7,1.2) 48(-0.7,0.7)
  rect 5.25x5.25 smd: 49(2.75,3.45)
QFNWB50P500X500X100-33N
  oval 0.3x0.851 smd: 1(0,0) 2(0.5,0) 3(1,0) 4(1.5,0) 5(2,0) 6(2.5,0) 7(3,0) 8(3.5,0) 17(3.5,4.9) 18(3,4.9) 19(2.5,4.9) 20(2,4.9) 21(1.5,4.9) 22(1,4.9) 23(0.5,4.9) 24(0,4.9)
  oval 0.851x0.3 smd: 9(4.2,0.7) 10(4.2,1.2) 11(4.2,1.7) 12(4.2,2.2) 13(4.2,2.7) 14(4.2,3.2) 15(4.2,3.7) 16(4.2,4.2) 25(-0.7,4.2) 26(-0.7,3.7) 27(-0.7,3.2) 28(-0.7,2.7) 29(-0.7,2.2) 30(-0.7,1.7) 31(-0.7,1.2) 32(-0.7,0.7)
  rect 3.25x3.25 smd: 33(1.75,2.45)
QFP40P1600X1600X120-128N
  oval 0.201x1.501 smd: 1(0,0) 2(0.399,0) 3(0.8,0) 4(1.199,0) 5(1.6,0) 6(1.999,0) 7(2.4,0) 8(2.799,0) 9(3.2,0) 10(3.599,0) 11(4,0) 12(4.399,0) 13(4.801,0) 14(5.199,0) 15(5.601,0) 16(6,0) 17(6.401,0) 18(6.8,0) 19(7.201,0) 20(7.6,0) 21(8.001,0) 22(8.4,0) 23(8.801,0) 24(9.2,0) 25(9.601,0) 26(10,0) 27(10.399,0) 28(10.8,0) 29(11.199,0) 30(11.6,0) 31(11.999,0) 32(12.4,0) 65(12.4,15.4) 66(11.999,15.4) 67(11.6,15.4) 68(11.199,15.4) 69(10.8,15.4) 70(10.399,15.4) 71(10,15.4) 72(9.601,15.4) 73(9.2,15.4) 74(8.801,15.4) 75(8.4,15.4) 76(8.001,15.4) 77(7.6,15.4) 78(7.201,15.4) 79(6.8,15.4) 80(6.401,15.4) 81(6,15.4) 82(5.601,15.4) 83(5.199,15.4) 84(4.801,15.4) 85(4.399,15.4) 86(4,15.4) 87(3.599,15.4) 88(3.2,15.4) 89(2.799,15.4) 90(2.4,15.4) 91(1.999,15.4) 92(1.6,15.4) 93(1.199,15.4) 94(0.8,15.4) 95(0.399,15.4) 96(0,15.4)
  oval 1.501x0.201 smd: 33(13.899,1.501) 34(13.899,1.9) 35(13.899,2.301) 36(13.899,2.7) 37(13.899,3.099) 38(13.899,3.5) 39(13.899,3.899) 40(13.899,4.3) 41(13.899,4.699) 42(13.899,5.1) 43(13.899,5.499) 44(13.899,5.9) 45(13.899,6.299) 46(13.899,6.7) 47(13.899,7.099) 48(13.899,7.501) 49(13.899,7.899) 50(13.899,8.301) 51(13.899,8.7) 52(13.899,9.101) 53(13.899,9.5) 54(13.899,9.901) 55(13.899,10.3) 56(13.899,10.701) 57(13.899,11.1) 58(13.899,11.501) 59(13.899,11.9) 60(13.899,12.301) 61(13.899,12.7) 62(13.899,13.099) 63(13.899,13.5) 64(13.899,13.899) 97(-1.501,13.899) 98(-1.501,13.5) 99(-1.501,13.099) 100(-1.501,12.7) 101(-1.501,12.301) 102(-1.501,11.9) 103(-1.501,11.501) 104(-1.501,11.1) 105(-1.501,10.701) 106(-1.501,10.3) 107(-1.501,9.901) 108(-1.501,9.5) 109(-1.501,9.101) 110(-1.501,8.7) 111(-1.501,8.301) 112(-1.501,7.899) 113(-1.501,7.501) 114(-1.501,7.099) 115(-1.501,6.7) 116(-1.501,6.299) 117(-1.501,5.9) 118(-1.501,5.499) 119(-1.501,5.1) 120(-1.501,4.699) 121(-1.501,4.3) 122(-1.501,3.899) 123(-1.501,3.5) 124(-1.501,3.099) 125(-1.501,2.7) 126(-1.501,2.301) 127(-1.501,1.9) 128(-1.501,1.501)
QFP50P700X700X120-32A2N
  custom 0.075x0.075 smd: 1(0,0) 2(0.5,0) 3(1,0) 4(1.5,0) 5(2,0) 6(2.5,0) 7(3,0) 8(3.5,0) 9(4.95,1.45) 10(4.95,1.95) 11(4.95,2.45) 12(4.95,2.95) 13(4.95,3.45) 14(4.95,3.95) 15(4.95,4.45) 16(4.95,4.95) 17(3.5,6.4) 18(3,6.4) 19(2.5,6.4) 20(2,6.4) 21(1.5,6.4) 22(1,6.4) 23(0.5,6.4) 24(0,6.4) 25(-1.45,4.95) 26(-1.45,4.45) 27(-1.45,3.95) 28(-1.45,3.45) 29(-1.45,2.95) 30(-1.45,2.45) 31(-1.45,1.95) 32(-1.45,1.45)
RESC0603X35N
  custom 0.105x0.105 smd: 1(0,0) 2(0.66,0)
RESC1005X40A2N
  custom 0.16x0.16 smd: 1(0,0) 2(0.9,0)
RESC1005X40B2N
  custom 0.125x0.125 smd: 1(0,0) 2(0.924,0)
RESC1005X40N
  custom 0.16x0.16 smd: 1(0,0) 2(0.9,0)
RESC1005X50A2N
  custom 0.16x0.16 smd: 1(0,0) 2(0.9,0)
RESC1608X55A2N
  custom 0.237x0.237 smd: 1(0,0) 2(1.6,0)
RESC1608X55N
  custom 0.237x0.237 smd: 1(0,0) 2(1.6,0)
RESC3216X75N
  custom 0.287x0.287 smd: 1(0,0) 2(3,0)
RESC3225X75N
  custom 0.287x0.287 smd: 1(0,0) 2(3,0)
RESC3246X70A2N
  custom 0.287x0.287 smd: 1(0,0) 2(2.9,0)
SAMTEC_FTSH-105-01-F-DV-K-10L
  oval 0.551x2.05 smd: 1(0,0) 2(0,4.6) 3(1.27,0) 4(1.27,4.6) 5(2.54,0) 6(2.54,4.6) 7(3.81,0) 8(3.81,4.6) 9(5.08,0) 10(5.08,4.6)
SAMTEC_SSQ11023LD_A2B
  round 1.65 hole 1.05: 1(0,0) 2(2.54,0) 3(0,2.54) 4(2.54,2.54) 5(0,5.08) 6(2.54,5.08) 7(0,7.62) 8(2.54,7.62) 9(0,10.16) 10(2.54,10.16) 11(0,12.7) 12(2.54,12.7) 13(0,15.24) 14(2.54,15.24) 15(0,17.78) 16(2.54,17.78) 17(0,20.32) 18(2.54,20.32) 19(0,22.86) 20(2.54,22.86)
SOIC127P600X175-8A2N
  custom 0.15x0.15 smd: 1(0,0) 2(1.27,0) 3(2.54,0) 4(3.81,0) 5(3.81,4.95) 6(2.54,4.95) 7(1.27,4.95) 8(0,4.95)
SOIC127P600X175-8N
  oval 0.6x1.55 smd: 1(0,0) 2(1.27,0) 3(2.54,0) 4(3.81,0) 5(3.81,5.4) 6(2.54,5.4) 7(1.27,5.4) 8(0,5.4)
SON50P100X145X60-6N
  custom 0.075x0.075 smd: 1(0,0) 2(0.5,0) 3(1.001,0) 4(1.001,0.589) 5(0.5,0.589) 6(0,0.589)
SON50P300X200X60-9B2L
  custom 0.075x0.075 smd: 1(0,0) 2(0.5,0) 3(1,0) 4(1.5,0) 5(1.5,2.4) 6(1,2.4) 7(0.5,2.4) 8(0,2.4)
  rect 1.7x0.3 smd: 9(0.75,1.2)
SON50P300X300X100-11A2N
  custom 0.062x0.062 smd: 1(0,0) 2(0.5,0) 3(1,0) 4(1.5,0) 5(2,0) 6(2,2.94) 7(1.5,2.94) 8(1,2.94) 9(0.5,2.94) 10(0,2.94)
  custom 0.412x0.412 smd: 11(1,1.47)
SON65P300X300X100-9A2N
  custom 0.087x0.087 smd: 1(0,0) 2(0.65,0) 3(1.3,0) 4(1.95,0) 5(1.95,2.87) 6(1.3,2.87) 7(0.65,2.87) 8(0,2.87)
  custom 0.375x0.375 smd: 9(0.975,1.435)
SON65P300X300X100-9AL
  custom 0.075x0.075 smd: 1(0,0) 2(0.65,0) 3(1.3,0) 4(1.95,0) 5(1.95,3) 6(1.3,3) 7(0.65,3) 8(0,3)
  rect 2.5x1.65 smd: 9(0.975,1.5)
SOP50P310X90-8N
  oval 0.3x0.851 smd: 1(0,0) 2(0.5,0) 3(1,0) 4(1.5,0) 5(1.5,3.1) 6(1,3.1) 7(0.5,3.1) 8(0,3.1)
SOP65P490X110-8N
  oval 0.4x1.4 smd: 1(0,0) 2(0.65,0) 3(1.3,0) 4(1.95,0) 5(1.95,4.4) 6(1.3,4.4) 7(0.65,4.4) 8(0,4.4)
SOP65P490X110-9B2N
  custom 0.113x0.113 smd: 1(0,0) 2(0.65,0) 3(1.3,0) 4(1.95,0) 5(1.95,4.3) 6(1.3,4.3) 7(0.65,4.3) 8(0,4.3)
  rect 1.9x1.6 smd: 9(0.975,2.15)
SOT65P210X110-5N
  oval 0.399x0.899 smd: 1(0,0) 2(0.65,0) 3(1.3,0) 4(1.3,2.2) 5(0,2.2)
SOT95P230X110-3N
  custom 0.15x0.15 smd: 1(0,0) 2(1.9,0) 3(0.95,2.3)
SOT95P237X130-3N
  oval 0.6x1.05 smd: 1(0,0) 2(1.9,0) 3(0.95,2.3)
SOT95P280X145-5A2N
  custom 0.15x0.15 smd: 1(0,0) 2(0.95,0) 3(1.9,0) 4(1.9,2.29) 5(0,2.29)
SW_1188E1K2V_A2N
  round 0.099 hole 0.899 unplated: (2.229,0.6) (4.529,0.6)
  custom 0.25x0.25 smd: 1(0,0) 2(6.75,0)
  custom 0.225x0.225 smd: 3(1.275,1.8) 4(5.475,1.8)
TAGCONNECT_TC2050IDCNL_A2N
  round 0.1 hole 1 unplated: (-1.27,0.635) (6.35,-0.38) (6.35,1.65)
  round 0.8 smd: 1(0,0) 2(1.27,0) 3(2.54,0) 4(3.81,0) 5(5.08,0) 6(5.08,1.27) 7(3.81,1.27) 8(2.54,1.27) 9(1.27,1.27) 10(0,1.27)
TRASH
  oval 0.025x0.051 smd: 1(0,0)
TSSOP65P640X120-21N
  oval 0.4x1.5 smd: 1(0,0) 2(0.65,0) 3(1.3,0) 4(1.95,0) 5(2.6,0) 6(3.25,0) 7(3.9,0) 8(4.55,0) 9(5.2,0) 10(5.85,0) 11(5.85,5.8) 12(5.2,5.8) 13(4.55,5.8) 14(3.9,5.8) 15(3.25,5.8) 16(2.6,5.8) 17(1.95,5.8) 18(1.3,5.8) 19(0.65,5.8) 20(0,5.8)
  rect 3x2 smd: 21(2.925,2.9)
unnamed#2
  round 0.099 hole 3.2 unplated: (0,0) (15,0)
XTAL_FC-135N
  custom 0.25x0.25 smd: 1(0,0) 2(2.499,0)

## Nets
5V0: C48.1 C103.1 C104.1 C121.1 C122.1 C149.2 C150.1 FL2.1 P4.19 TP10.1 U7.1 U7.2 U7.8 U18.1 U18.3 U20.6 U20.7 U27.1 U27.3
5V0_BP: J1.2 P2.1 P4.20
GND: C1.2 C2.2 C3.2 C4.2 C5.2 C6.2 C7.2 C8.2 C9.2 C11.2 C30.2 C31.2 C33.2 C34.2 C35.2 C38.2 C39.2 C40.2 C41.2 C42.2 C43.2 C44.2 C45.2 C46.2 C48.2 C49.2 C50.2 C51.2 C52.2 C53.2 C54.2 C55.2 C56.2 C57.2 C61.2 C62.1 C63.2 C64.1 C65.2 C66.1 C67.2 C68.2 C69.1 C70.2 C71.2 C72.2 C73.2 C75.2 C76.2 C77.2 C78.2 C79.2 C80.2 C83.2 C84.2 C85.1 C86.1 C87.2 C88.1 C89.1 C90.2 C92.2 C93.2 C94.2 C96.2 C97.2 C98.2 C99.2 C100.2 C101.2 C102.2 C103.2 C104.2 C105.2 C106.2 C107.1 C108.2 C109.1 C110.2 C111.2 C112.2 C114.2 C115.2 C116.2 C117.2 C118.2 C119.2 C121.2 C122.2 C123.2 C124.2 C125.2 C127.2 C128.2 C130.2 C131.2 C132.2 C137.2 C138.2 C139.2 C140.2 C141.2 C142.2 C143.2 C144.2 C145.2 C146.2 C147.2 C149.1 C150.2 C151.2 C221.2 C222.2 C231.2 C232.2 C331.2 C341.2 C342.2 C351.2 C441.2 C451.2 C481.2 CR1.1(C) CR2.1(C) CR4.1(C) CR5.1(C) CR6.3 CR7.4 CR8.4 CR9.2 J1.4 J2.2 J6.5 J7.2 J7.3 J7.4 J7.5 L26.2 MH3.1 MH4.1 MH5.1 P1.2 P1.3 P2.2 P2.3 P4.21 P4.22 P5.3 P5.5 P5.9 P7.3 P7.5 P7.9 P8.3 P8.5 P8.9 R21.2 R28.1 R29.2 R30.2 R32.1 R34.1 R61.1 R62.1 R63.1 R65.1 R74.1 R84.1 R85.1 R92.1 R94.1 R101.1 R104.2 R113.1 R114.1 R116.2 R118.1 R120.1 R124.1 R125.1 R126.2 R127.2 R128.2 R129.2 R137.1 SW1.1 SW1.2 SW1.3 SW2.1 SW2.2 SW2.4 SW3.1 SW3.2 SW3.4 U1.49 U4.4 U4.9 U5.10 U5.17 U5.48 U5.55 U5.58 U5.64 U5.66 U5.80 U5.114 U6.1 U7.6 U7.9 U8.1 U8.5 U8.7 U8.10 U8.11 U8.16 U9.1 U9.5 U9.10 U9.11 U9.13 U9.16 U10.7 U10.9 U10.10 U10.11 U10.12 U10.16 U11.2(V-) U12.5 U14.4 U15.1 U15.2 U15.33 U16.3 U16.5 U16.10 U16.13 U16.14 U16.15 U16.16 U16.18 U16.26 U16.29 U16.30 U16.31 U17.4 U18.2 U19.2 U19.3 U19.19 U19.25 U20.1 U20.2 U20.3 U20.5 U20.9 U20.10 U20.11 U20.12 U20.19 U20.20 U20.21 U21.4 U21.9 U22.4 U22.9 U24.7 U24.10 U24.11 U24.12 U25.6 U25.11 U26.6 U26.7 U26.8 U26.9 U26.10 U26.11 U27.2 Y2.2 Y2.4(GND#4) Y3.2 Y3.4 Y4.2 Y4.4 Y5.2 Z61.2 Z62.2
VBUS_DET: R115.1 R116.1 U5.12
VDD_SWITCH: C144.1 C145.1 C146.1 R136.1 U24.14(VCC) U25.1(VCC) U26.1(VCC) U27.5(OUT)
VDDC: C43.1 C44.1 C45.1 U5.87(VDDC#87) U5.115
VDDR: C331.1 C451.1 C481.1 L331.2 U1.45 U1.48
VDDS: C131.1 C132.1 C221.1 C222.1 C341.1 C342.1 C441.1 FL1.1 R351.2 U1.13 U1.22 U1.34 U1.44
BP_RESET: J2.11 R52.1
CAL_VDD: U24.2 U24.4 U24.9 U26.2
DCDC_SW: L331.1 U1.33
DIO1: J1.20 U1.6
DIO4_SCL: J1.17 R2.1 U1.9
DIO5_SDA: J1.19 R3.1 U1.10
DIO6_RLED: J2.3 P6.2 U1.11
DIO7_GLED: J2.1 P6.4 U1.12
DIO8_MISO: J2.14 U1.14 U4.2
DIO9_MOSI: J2.12 U1.15(DIO_9) U4.5
DIO10_SCLK: J1.13 U1.16 U4.6
DIO11_CS: J2.6 U1.17
DIO12: J2.4 U1.18
DIO13_BTN1: J2.16 R56.2 U1.19
DIO14_BTN2: J2.18 R55.2 U1.20
DIO15: J2.20 U1.21
DIO16_TDO: CR8.5 P4.6 P5.6 R48.2 U1.26
DIO17_TDI: CR8.3 P4.4 P5.8 R49.2 U1.27
DIO19_CTS: J2.7 U1.29
DIO20_FLASH_CS: J2.5 R11.1 U1.30 U4.1
DIO21: J1.15 U1.31
DIO22: J1.9 U1.32
DIO23_ANALOG: J1.3 U1.36
DIO24_ANALOG: J1.11 U1.37
DIO25_ANALOG: J1.6 U1.38
DIO26_ANALOG: J1.8 U1.39
DIO27_ANALOG: J1.10 U1.40
DIO28_ANALOG: J1.12 U1.41
DIO29_ANALOG: J1.14 U1.42
DIO30_ANALOG: J1.16 U1.43
ET_1V8: C94.1 C105.1 C106.1 TP6.1 U16.1 U18.5(OUT)
ET_3V3: C70.1 C75.1 C107.2 C123.1 C124.1 C125.1 C126.2 L23.1 L24.2 Q2.2(S) R96.2 R103.1 TP1.1 U11.5 U14.2 U19.5 U19.6 U20.13 U20.14
ET_+12V: C63.1 C65.1 C68.1 C128.1 C130.1 C135.1 R117.2 TP4.1 U12.7 U13.7 U21.1(OUT)
ET_-12V: C64.2 C66.2 C69.2 C136.1 C139.1 C140.1 R119.2 TP2.1 U12.4(V-) U13.4 U22.1(OUT)
ET_AVDD: C99.1 C100.1 C101.1 C102.1 L24.1 R93.1 U16.6 U16.32
ET_CAL0: R126.1 U5.74 U24.13
ET_CAL1: R127.1 U5.73 U24.5
ET_CAL2: R129.1 U5.23 U24.6
ET_CALIBRATE: TP15.1 U5.77 U26.4
ET_DVDD: C97.1 C98.1 L22.1 L23.2 R106.2 R110.1 U16.12 U16.27 Y5.1
ET_PM2: R106.1 U5.76 U16.17(START)
ET_PN3: R110.2 U5.110 U16.28
ET_SSICLK: U5.120 U16.22
ET_SSIDAT0: U5.123 U16.21
ET_SSIDAT1: U5.124 U16.20
ET_SSIFSS: U5.121 U16.19
IRSTN: P8.10 R20.2
ITCK: P8.4 U5.100
ITDI: P8.8 U5.98
ITDO: P8.6 U5.97
ITMS: P8.2 U5.99
LP_RESET: J2.10 R51.1
REF5025: C90.1 R79.1 R80.1 R81.1 TP8.1 U16.9
RX_TX: C31.1 L32.2 U1.3
SENSE_R_BYPASS: TP14.1 U5.78 U25.4 U25.8
TARGET_VDD: P4.17 U26.5
USB1V8: C83.1 C84.1 C85.2 U15.15 U15.26
USB_VBUS: C77.1 C82.1 CR6.6 J6.1(VCC) Q1.2(S) R82.2 R86.2 R115.2
USBCLK: U5.92 U15.14
USBD0: U5.81 U15.24
USBD1: U5.82 U15.23
USBD2: U5.83 U15.22
USBD3: U5.84 U15.21
USBD4: U5.85 U15.20
USBD5: U5.86 U15.19
USBD6: U5.106 U15.18
USBD7: U5.105 U15.17
USBDIR: U5.104 U15.12
USBDM: CR6.5 J6.2 U15.8
USBDP: CR6.4 J6.3 U15.7
USBID: CR6.2 J6.4
USBNXT: U5.103 U15.11
USBSTP: U5.91 U15.13
V-SENSE: C53.1 C55.1 C57.1 CR7.8(VCC) P7.1 P10.2 U8.2(VCCB) U9.2(VCCB) U10.2(VCCB) U25.3 U25.9
VM_SOURCE_VN: R69.2 R76.1 TP13.1 U25.7 U26.3
VM_SOURCE_VP: R70.2 R76.2 TP12.1 U25.2
WMCU_RESET: C351.1 CR8.2 P4.12 P5.10 R51.2 R52.2 R351.1 U1.35
WMCU_RXD: J1.5 P4.16 U1.7
WMCU_SWO: J2.9 P4.2 U1.28
WMCU_TCK: CR8.6 P4.8 P5.4 R47.2 U1.25
WMCU_TMS: CR8.7 P4.10 P5.2 R46.2 U1.24
WMCU_TXD: J1.7 P4.14 U1.8
WMCU_VDD: CR8.8(VCC) FL1.2 J1.1 P1.1 P4.18 P5.1 P10.3 R2.2 R3.2 R11.2 R59.2 R60.2 R133.2
XDS_RESET: R58.1 U5.40 U10.1 U10.6
XDS_RESET_LS: CR7.2 P4.11 P7.10 R57.2 U10.15
XDS_RX: U5.33 U8.8
XDS_RX_LS: P4.13 R61.2 U8.13
XDS_SWO: U5.25 U8.9
XDS_SWO_LS: P4.1 R62.2 U8.12
XDS_TCK: U5.35 U9.6
XDS_TCK_LS: CR7.6 P4.7 P7.4 U9.15
XDS_TDI: U5.38 U9.7
XDS_TDI_LS: CR7.3 P4.3 P7.8 U9.14
XDS_TDO: U5.37 U9.9
XDS_TDO_LS: CR7.5 P4.5 P7.6 R63.2 U9.12
XDS_TMS: U5.36 U10.8
XDS_TMS_DIR: U5.24 U10.5
XDS_TMS_LS: CR7.7 P4.9 P7.2 R65.2 U10.13
XDS_TX: U5.34 U8.6
XDS_TX_LS: P4.15 U8.15
XDS_VCC: C2.1 C3.1 C4.1 C6.1 C7.1 C38.1 C39.1 C40.1 C42.1 C47.1 C49.1 C52.1 C54.1 C56.1 C78.1 C79.1 C80.1 P8.1 P10.1 R17.2 R18.2 R27.1 R31.2 R33.2 R39.1 R58.2 R83.1 TP11.1 U5.7 U5.8 U5.16 U5.26 U5.28 U5.39 U5.47 U5.51 U5.52 U5.69 U5.79 U5.90 U5.101 U5.113 U5.122 U7.3 U7.4(OUT#4) U8.3 U8.4 U9.3 U9.4 U10.3 U10.4 U15.6 U15.16 U15.25 U15.30 U15.31
N949215: R17.1 R20.1 R21.1 U5.70
N949243: R30.1 U5.60
N949263: C47.2 R33.1 R34.2 U7.5
N949375: R28.2 U5.59
N949687: C1.1 U5.89 Y3.3
N949695: C9.1 U5.88 Y3.1
N950083: C8.1 C50.1 R18.1 U5.9 U6.3
N951001: R39.2 U5.63
N951013: R29.1 U5.61
N951017: R27.2 U5.62
N952443: C46.1 R31.1 U5.68
N1004371: R23.2 U5.3
N1004534: R25.2 U5.4
N1013277: U1.46 Y2.3
N1014101: C41.1 U1.4 Y1.1
N1014113: C51.1 U1.5 Y1.2
N1017630: C30.1 R133.1 U4.8(VCC)
N1018952: U1.47 Y2.1
N1031635: CR6.1 J6.M1 J6.M2 R32.2
N1105722: CR1.2 R15.1
N1105771: CR2.2 R14.1
N1105824: P6.1 R14.2
N1106228: P6.3 R15.2
N1176544: J2.13 R46.1
N1176548: J2.15 R47.1
N1176568: J2.17 R48.1
N1177007: J2.19 R49.1
N1288065: R55.1 SW2.3
N1288098: R56.1 SW1.4
N1384129: R57.1 SW3.3
N1409884: R59.1 U4.3
N1409917: R60.1 U4.7
N1532633: C60.1 C62.2 R69.1 U12.2
N1532640: C60.2 C61.1 R70.1 U12.3
N1532863: R71.2 U12.1
N1532870: R71.1 U12.8
N1536103: C67.1 CR9.1(CATHODE) R72.1 TP7.1 U16.4
N1536178: TP9.1 U12.6 U13.3
N1536208: R73.2 R74.2 U13.2
N1536226: R72.2 R73.1 U13.6
N1540868: C71.1 U14.5
N1541303: R77.2 R78.2 U14.6(VOUT)
N1541344: C73.1 R78.1 U11.3
N1541677: C74.1 R79.2 U11.4
N1541715: C74.2 R80.2 U11.1
N1542217: C76.1 R81.2
N1548408: R82.1 U15.4
N1553941: R83.2 U15.5
N1559020: C82.2 Q1.1 R85.2
N1559161: C151.1 FL2.2 Q1.3 R86.1
N1567630: C86.2 C87.1 U15.29
N1579665: R84.2 U15.32
N1580179: C88.2 R87.2 U15.28 Y4.1
N1580186: C89.2 R87.1 U15.27(XO) Y4.3
N1589081: C5.1 U16.2
N1589096: C92.1 U16.11
N1589103: C93.1 U16.25
N1594429: C96.1 C147.1 L22.2 U17.6 U17.7 U17.8(VCC) Y5.4(VDD)
N1594693: U17.1 Y5.3
N1594702: R131.2 U16.24
N1594966: U17.2 U17.3
N1594995: R131.1 U17.5
N1595900: R92.2 U16.7
N1605224: R93.2 U16.8
N1605907: R94.2 U16.23
N1644260: R114.2 U5.95
N1644363: R113.2 U5.96
N1687235: C108.1 R96.1 U19.4 U19.8 U19.9 U19.10 U19.11
N1687263: Q2.1 U19.7
N1687273: C109.2 L25.1 Q2.3
N1687279: CR10.2 L25.2 U19.1 U19.24
N1687281: C115.1 C116.1 C118.1 C127.1 CR10.1(CATHODE) R97.1 R102.1 TP5.1 U19.23 U21.5 U21.8
N1687325: C110.1 U19.21
N1687331: C111.1 U19.18
N1687341: C120.1 R97.2 R101.2 U19.22
N1687345: CR11.1(CATHODE) L26.1 U19.13 U19.14
N1687359: C114.1 C117.1 C119.1 C232.1 CR11.2 R98.2 R100.1 TP3.1 U19.15 U22.5 U22.8
N1687363: C113.1 R98.1 R99.1 U19.16
N1687373: C112.1 R99.2 U19.17(VREF)
N1687391: C113.2 R100.2
N1687461: C120.2 R102.2
N1687583: C126.1 R103.2 R104.1 U20.15
N1687761: C135.2 R117.1 R118.2 U21.2
N1687779: C137.1 U21.6
N1687817: C138.1 U22.6
N1687829: C136.2 R119.1 R120.2 U22.2
N1699637: C141.1 R124.2 U24.1
N1715528: C142.1 R125.2 U24.3
N1716003: C143.1 R128.1 U24.8
N1936147: R136.2 R137.2 U27.4
N2070550: C231.1 U1.23
N2071733: C11.1 L11.1 L12.2 U1.1
N2072219: C21.1 L12.1 L32.1 U1.2
N2075216: C21.2 C33.1 L11.2 L33.1
N2075665: C34.1 L33.2 L34.1
N2076038: C35.1 C36.1 C37.1 L34.2
N2078765: C37.2 J7.1
N2082297: Z60.2 Z61.1 Z62.1 Z63.1
N2245591: A1.1 Z63.2
N2266542: C36.2 Z60.1
N10367920: CR5.2 R25.1
N10368080: CR4.2 R23.1
N15411560: C72.1 R77.1

Pads without a net: CR7 1; CR8 1; FIDU1 1; FIDU2 1; FIDU3 1; FIDU4 1; FIDU5 1; FIDU6 1; J1 18; J2 8; LBL5 1; LBL6 1; MH1 1; MH2 1; P5 7; P7 7; P8 7; U5 1 2 5 6 11 13 14 15 18 19 20 21 22 27 29 30 31 32 41 42 43 44 45 46 49 50 53 54 56 57 65 67 71 72 75 93 94 102 107 108 109 111 112 116 117 118 119 125 126 127 128; U6 2 4 5; U7 7; U8 14; U9 8; U10 14; U13 1 5 8; U14 1 3 7 8; U15 3 9 10; U18 4; U19 12 20; U20 4 8 16 17 18; U21 3 7; U22 3 7; U25 5 10

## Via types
v1: diameter 0.4, hole 0.2, TOP to BOTTOM, 1076 vias
v2: diameter 0.5, hole 0.201, TOP to BOTTOM, 25 vias

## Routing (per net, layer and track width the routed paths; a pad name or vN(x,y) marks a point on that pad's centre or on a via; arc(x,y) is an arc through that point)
5V0: length 121.8
  TOP w0.15: TP10.1 56.25,99.3 U18.1
  TOP w0.3: v1(2.71,84.56) 2.27,85 U27.3 1.45,85 0.92,85.52 0.92,86.3 1.52,86.9 U27.1 ; C104.1 55.72,103.42 C103.1 55.76,103.45 56.21,103 56.21,102.99 56.25,102.95 U18.3 55.85,102.1 v1(55.25,101.5) 55.25,100.82 55.88,100.2 U18.1 ; C48.1 16.1,113.35 U7.2 ; C48.1 16.05,113.25 ; C48.1 16.05,113.6 16.45,114 U7.1
  BOTTOM w0.3: v1(25.35,114.6) 25.9,114.05 31.56,114.05 31.76,113.85 52.29,113.85 54.2,111.94 54.2,111.56 54.2,111.56 54.2,102.55 v1(55.25,101.5) ; 13.95,84.8 P4.19 ; 13.95,84.8 13.95,88.3 12.35,89.9 5,89.9 3.6,91.3 3.6,95.9 5.35,97.65 7.9,97.65 13.65,103.4 18.89,103.4 20.25,104.76 20.25,105.4 19.55,106.1 19.55,113.45 18.55,114.45 v1(16.55,114.45) ; 13.95,84.8 13.71,84.56 10.37,84.56 10.21,84.4 8.64,84.4 8.48,84.56 v1(2.71,84.56)
5V0_BP: length 53.7
  BOTTOM w0.5: J1.2 8.87,73.54 ; 8.87,73.54 3.65,68.32 3.65,38.12 P2.1 ; 8.87,73.54 P4.20
GND: length 259.4
  TOP w0.15: Y3.2 2.5,107.15 v1(2.8,106.85) ; 5.6,112.25 C77.2 ; v1(44.3,112.55) 43.97,112.88 C61.2 ; 5.49,37.1 P2.2 7.21,38.82 ; 9.73,66.78 J1.4 8.01,65.06 ; 10.55,80.3 P4.21 12.27,82.02 ; R125.1 42.5,113.05 42.47,113.08 v1(42.07,113.08) ; C79.2 14.06,109.44 C80.2 ; v1(34.55,43.55) 34.52,43.52 C41.2 33.85,44.16 33.9,44.21 C51.2 34.57,44.68 v1(34.6,44.65) ; C150.2 20.68,112.7 U7.6 ; 52.07,67.38 52.07,67.55 ; 51.21,67.6 J2.2 52.94,69.32 ; 5.49,39.64 P2.3 7.21,41.36 ; 52.1,113.65 R74.1 50.8,113.65 U12.5 ; v1(18.75,29.35) 18.65,29.35 ; 7.43,40.5 7.3,40.5 ; C87.2 v1(14.7,107.9) ; 11.41,77.54 11.41,77.75 ; 51,68.46 51.2,68.46 ; 10.55,77.76 P4.22 10.34,78.62 ; 11.41,82.24 11.41,82.22 ; U19.2 31.68,93.7 C108.2 31.52,93.2 U19.3 ; 52.91,38.82 P1.2 51.19,37.1 ; 52.91,41.36 P1.3 51.19,39.64 ; 5.97,72.7 5.99,72.7 ; v1(42.4,118.45) 42.86,118.45 43.6,117.71 C62.1 ; 52.05,36.88 52.05,37.05 ; 8.87,67 8.87,66.75
  TOP w0.201: U7.9 18.85,112.62 v1(18.85,112.25) ; U7.9 17.87,112.45 C49.2 ; U7.9 18.43,113.04 v1(18.43,113.79) ; v1(10.9,108.9) 11.1,109.1 ; 11.1,109.1 11.6,109.6 U15.1 ; 11.1,109.1 U15.2 ; 50.8,92.25 51.07,92.25 51.57,91.75 C71.2 51.62,91.33 v1(51.65,91.3)
  TOP w0.3: 56.45,78.25 55.92,78.25 54.65,76.97 ; 13.85,112.32 12.65,113.52 J6.5
  TOP w0.7: P2.3 6.35,39.42 ; P2.3 6.35,41.58 ; P2.3 5.27,40.5 ; P2.3 7.3,40.5 ; J2.2 53.15,68.46 ; J2.2 51.2,68.46 ; J2.2 52.07,67.55 ; P1.2 53.13,37.96 ; P1.2 P1.3 ; P1.2 50.76,37.96 ; P1.2 52.05,37.05 ; P2.2 5.27,37.96 ; P2.2 6.35,39.2 ; P2.2 6.35,36.88 ; P2.2 7.43,37.96 ; 50.97,40.5 P1.3 ; P1.3 53.13,40.5 ; P1.3 52.05,41.58 ; 11.41,79.86 P4.22 ; P4.22 11.38,78.65 10.2,78.65 ; P4.22 12.49,78.62 ; P4.22 11.41,77.75 ; 8.87,66.75 J1.4 ; J1.4 9.95,65.92 ; J1.4 8.87,64.84 ; J1.4 7.8,65.92 ; 11.41,80.08 P4.21 ; P4.21 10.34,81.16 ; P4.21 12.49,81.16 ; P4.21 11.41,82.22
  L2 w0.15: 11.41,82.24 11.41,82.22 ; 7.8,65.92 7.95,65.92 ; 7.21,38.82 P2.2 5.49,37.1 ; 52.91,38.82 P1.2 51.19,37.1 ; 51.21,67.6 J2.2 52.94,69.32 ; 6.35,39.42 6.35,39.65 ; 54.13,118.32 MH4.1 54.13,115.08 ; 6.35,39.04 6.35,38.85 ; 4.07,118.32 MH3.1 0.83,115.08 ; 5.49,39.64 P2.3 7.21,41.36 ; 12.27,79.48 P4.22 10.55,77.76 ; 3.83,82.48 MH5.1 2.07,80.72 ; 9.73,66.78 J1.4 8.01,65.06 ; 12.27,82.02 P4.21 10.55,80.3 ; 11.41,80.08 11.41,80.3 ; 8.87,64.84 8.87,65.05 ; 52.91,41.36 P1.3 51.19,39.64 ; 12.49,78.62 12.3,78.62
  L2 w0.7: 4.6,116.7 MH3.1 2.45,114.55 ; P1.2 52.05,39.04 ; P1.2 50.97,37.96 ; P1.2 53.13,37.96 ; P1.2 52.05,36.88 ; P2.3 6.35,41.58 ; P2.3 7.43,40.5 ; P2.3 5.27,40.5 ; P2.3 6.35,39.65 ; P4.22 11.41,77.54 ; P4.22 10.34,78.62 ; P4.22 12.3,78.62 ; P4.22 11.41,79.7 ; 8.87,65.05 J1.4 ; J1.4 8.87,67 ; J1.4 7.95,65.92 ; J1.4 9.95,65.92 ; P1.3 53.13,40.5 ; P1.3 50.97,40.5 ; P1.3 52.05,41.58 ; P1.3 52.05,39.42 ; 53.6,116.7 MH4.1 55.75,114.55 ; J2.2 52.07,69.54 ; J2.2 52.07,67.38 ; J2.2 51,68.46 ; J2.2 53.15,68.46 ; 4.1,81.6 MH5.1 ; MH5.1 1.85,81.6 ; MH5.1 2.95,80.5 ; MH5.1 2.95,82.7 ; P2.2 6.35,36.88 ; P2.2 7.43,37.96 ; P2.2 5.27,37.96 ; P2.2 6.35,38.85 ; P4.21 10.34,81.16 ; P4.21 12.49,81.16 ; P4.21 11.41,80.3 ; P4.21 11.41,82.22
  L3 w0.15: P1.3 52.05,41.58 ; P1.3 50.97,40.5 ; P1.3 52.05,39.42 ; 5.27,37.96 P2.2 ; P2.2 7.43,37.96 ; P2.2 6.35,39.04 ; P2.2 6.35,36.88 ; P2.3 6.35,41.58 ; P2.3 5.27,40.5 ; P2.3 6.35,39.42 ; P2.3 7.43,40.5 ; MH5.1 4.05,81.6 ; MH5.1 2.95,80.5 ; MH5.1 1.85,81.6 ; MH5.1 2.95,82.7 ; 52.05,39.04 P1.2 52.54,39.07 ; 11.41,80.08 P4.21 ; P4.21 12.49,81.16 ; P4.21 11.41,82.24 ; P4.21 10.34,81.16 ; J2.2 52.07,69.54 ; J2.2 51,68.46 ; J2.2 52.07,67.38 ; P4.22 11.41,79.7 ; P4.22 12.49,78.62 ; P4.22 10.34,78.62 ; J1.4 8.87,67 ; J1.4 9.95,65.92 ; J1.4 8.87,64.84 ; J1.4 7.8,65.92 ; 4.6,116.7 MH3.1 2.45,114.55 ; 54.13,118.32 MH4.1 57.37,115.08
  BOTTOM w0.15: 7.21,38.82 P2.2 5.49,37.1 ; v1(1.58,108.18) 1.6,108.18 1.6,108.2 P8.3 ; 52.07,67.38 52.07,67.55 ; 12.49,78.62 12.3,78.62 ; 51.1,102.35 51.1,102.35 ; 6.35,36.88 6.35,37.1 ; 8.01,65.06 J1.4 9.73,66.78 ; 52.05,39.04 52.05,38.85 ; 29.85,89.9 29.87,89.88 ; 10.55,80.3 P4.21 12.27,82.02 ; 51.19,39.64 P1.3 52.91,41.36 ; 8.87,67 8.87,66.85 ; 6.35,39.04 6.35,38.85 ; 52.05,36.88 52.05,37.1 ; 51.21,67.6 J2.2 52.94,69.32 ; 7.21,41.36 P2.3 5.49,39.64 ; 12.27,79.48 P4.22 10.55,77.76 ; 6.35,39.42 6.35,39.6 ; 12.49,81.16 12.3,81.16 ; 51.19,37.1 P1.2 52.91,38.82 ; 35.7,87.25 35.7,87.25 ; 11.41,82.24 11.41,82.22 ; 5.27,37.96 5.5,37.96 ; P8.9 2.81,107.51 2.8,107.5 v1(2.8,106.85) ; 8.87,64.84 8.87,65 ; 30.23,89.88 30.25,89.9 ; 7.8,65.92 8,65.92
  BOTTOM w0.7: 10.34,78.62 P4.22 ; P4.22 P4.21 ; P4.22 12.3,78.62 ; P4.22 11.41,77.54 ; P4.21 12.3,81.16 ; P4.21 11.41,82.22 ; P4.21 10.34,81.16 ; 6.35,38.85 P2.2 ; P2.2 7.43,37.96 ; P2.2 5.5,37.96 ; P2.2 6.35,37.1 ; 51,68.46 J2.2 ; J2.2 52.07,67.55 ; J2.2 53.15,68.46 ; J2.2 52.07,69.54 ; 52.05,37.1 P1.2 ; P1.2 50.97,37.96 ; P1.2 52.05,38.85 ; P1.2 53.13,37.96 ; 52.05,39.42 P1.3 ; P1.3 52.05,41.58 ; P1.3 50.97,40.5 ; P1.3 53.13,40.5 ; 6.35,39.6 P2.3 ; P2.3 5.27,40.5 ; P2.3 6.35,41.58 ; P2.3 7.43,40.5 ; J1.4 9.95,65.92 ; J1.4 8.87,65 ; J1.4 8,65.92 ; J1.4 8.87,66.85
  vias: v1(0.65,35.45) v1(0.65,31.8) v1(0.8,92.95) v1(0.8,68.35) v1(0.75,64.6) v1(0.75,57.3) v1(0.8,51.05) v1(0.7,39.55) v1(0.7,28.95) v1(0.85,93.95) v1(0.9,69.8) v1(0.85,44.1) v1(1.1,62.55) v1(1.55,27.05) v1(1.65,94.9) v1(1.6,91.1) v1(1.8,37.55) v1(2.05,97.4) v1(2,56.2) v1(2.35,100.4) v1(2.45,113.75) v1(2.45,65.3) v1(2.45,40.8) v1(2.55,53.9) v1(2.65,68.5) v1(2.6,61.55) v1(2.65,57.85) v1(2.8,77) v1(3,103.95) v1(3,70.2) v1(3.05,49.7) v1(3.2,31.85) v1(3.15,28.9) v1(3.55,85.7) v1(3.5,35.35) v1(3.6,71.5) v1(3.9,105.25) v1(4,78.5) v1(4.3,75.75) v1(4.25,74) v1(4.45,47.65) v1(4.6,113.1) v1(4.6,39.05) v1(5.03,106.5) v1(5.05,105.85) v1(5.05,100.95) v1(5,30.45) v1(5.12,107.52) v1(5.15,102) v1(5.15,28.25) v1(5.25,74.8) v1(5.25,51.15) v1(5.25,48.95) v1(5.35,95.1) v1(5.6,77.05) v1(5.6,42.2) v1(5.95,111) v1(5.95,32.5) v1(6.05,100.7) v1(6.1,102) v1(6.4,96.9) v1(6.45,111.25) v1(6.65,93.35) v1(6.8,43.4) v1(6.95,78.1) v1(7.15,75.7) v1(7.65,63.85) v1(7.65,62.15) v1(7.6,56.9) v1(7.6,52) v1(7.65,44.5) v1(7.7,69.9) v1(7.7,49.55) v1(7.95,26.95) v1(8.15,40.5) v1(8.25,38.35) v1(8.65,109) v1(8.65,33.4) v1(8.6,29.9) v1(8.85,89.2) v1(9,107) v1(9.05,35.85) v1(9.15,78.15) v1(9.4,43.35) v1(9.8,102) v1(9.7,71.4) v1(9.85,107.85) v1(10.05,79.95) v1(10,59.25) v1(10.15,31.55) v1(10.3,56.65) v1(10.3,41.15) v1(10.4,46.6) v1(10.55,67.05) v1(10.55,60.55) v1(10.55,39.25) v1(10.6,52) v1(10.79,53.95) v1(10.7,49) v1(10.85,107.02) v1(10.85,68.65) v1(10.9,62.45) v1(10.95,58.3) v1(11,93.95) v1(11,28.65) v1(11.3,98.15) v1(11.27,86.1) v1(11.25,65.1) v1(11.4,69.75) v1(11.55,102.1) v1(11.51,82.9) v1(11.65,35.35) v1(11.85,89.2) v1(12.15,110.4) v1(12.2,55.25) v1(12.25,111.7) v1(12.4,60.75) v1(12.45,68.85) v1(12.55,82.65) v1(12.5,58.6) v1(12.55,56.6) v1(12.5,42.4) v1(12.67,79.95) v1(12.75,62.7) v1(12.75,52.1) v1(12.8,44.65) v1(12.7,39.5) v1(12.85,86.35) v1(12.95,73.15) v1(13,66.25) v1(13.19,64.35) v1(13.15,49.8) v1(13.25,72.25) v1(13.25,47.3) v1(13.4,33.2) v1(13.55,29.8) v1(13.5,26.95) v1(13.8,55.45) v1(13.7,36.45) v1(13.9,41.1) v1(13.95,61.15) v1(14.07,95.85) v1(14,67.2) v1(14.1,90) v1(14.15,70.2) v1(14.2,58.9) v1(14.15,56.95) v1(14.3,112.15) v1(14.25,104.7) v1(14.3,48.75) v1(14.35,38.9) v1(14.5,110.2) v1(14.65,83.15) v1(14.95,63.15) v1(14.95,51.7) v1(15,72.8) v1(15,65.6) v1(15.15,79.45) v1(15.15,71.7) v1(15.1,68.3) v1(15.15,54.05) v1(15.35,60.05) v1(15.75,84.1) v1(15.8,31.95) v1(15.9,69.65) v1(15.9,55.2) v1(16.05,85.8) v1(16,57.2) v1(16.2,64.7) v1(16.3,29.15) v1(16.4,61.55) v1(16.45,107.75) v1(16.7,72.35) v1(16.8,49.8) v1(16.7,38.25) v1(16.7,35.7) v1(16.85,42.85) v1(16.95,116.35) v1(16.95,58.2) v1(16.95,47.85) v1(17,56) v1(17.19,68.35) v1(17.2,63) v1(17.25,102.1) v1(17.25,85.7) v1(17.4,95.65) v1(17.55,66.85) v1(17.65,89.85) v1(17.6,70.15) v1(17.75,98.1) v1(17.8,52.1) v1(17.9,109.6) v1(17.83,107) v1(17.85,99.4) v1(17.9,92.75) v1(17.85,91.95) v1(18.05,112.45) v1(18.05,108.8) v1(18,84.1) v1(18,65.05) v1(18.03,57.1) v1(18,37.8) v1(18.05,26.9) v1(18.1,101.9) v1(18.2,83.7) v1(18.15,71.75) v1(18.2,60.9) v1(18.19,59.3) v1(18.3,111.45) v1(18.3,104.65) v1(18.4,73) v1(18.5,118.25) v1(18.6,36.15) v1(18.79,50.7) v1(18.8,31.45) v1(19.05,47.6) v1(19,34.3) v1(19.15,85.3) v1(19.15,69.2) v1(19.15,62.6) v1(19.3,41.9) v1(19.3,40.3) v1(19.45,65.75) v1(19.47,61.25) v1(19.43,58.2) v1(19.43,55.9) v1(19.5,38.8) v1(19.6,67.6) v1(19.65,42.95) v1(20.05,109) v1(20.15,72.35) v1(20.15,63.8) v1(20.2,37.05) v1(20.25,115.95) v1(20.3,84.2) v1(20.3,35.6) v1(20.4,49.1) v1(20.47,59.4) v1(20.43,56.95) v1(20.47,55.4) v1(20.67,111.89) v1(20.63,50.05) v1(20.67,44.2) v1(20.75,105) v1(20.77,88.01) v1(20.7,51.7) v1(20.85,41.15) v1(20.85,39.65) v1(20.91,58.15) v1(21.05,67.95) v1(21,47) v1(21.15,70.15) v1(21.2,65.6) v1(21.2,42.9) v1(21.25,94.9) v1(21.4,88.4) v1(21.31,63.2) v1(21.35,61.8) v1(21.35,60.15) v1(21.4,31.5) v1(21.55,36.65) v1(21.55,34.35) v1(21.6,29) v1(21.8,47.25) v1(21.9,83.85) v1(21.95,118.3) v1(22.05,49.6) v1(22.2,95.4) v1(22.1,38.2) v1(22.1,26.95) v1(22.3,72.05) v1(22.35,41) v1(22.45,76.4) v1(22.55,100) v1(22.67,46.7) v1(22.6,42.15) v1(22.7,60.15) v1(22.7,43.35) v1(22.8,40.15) v1(22.87,66.15) v1(22.9,63.05) v1(22.85,51.5) v1(22.84,48.09) v1(23,61.45) v1(23,57.6) v1(23.2,69.8) v1(23.2,67.25) v1(23.2,37.2) v1(23.15,35.45) v1(23.15,33.45) v1(23.15,28.25) v1(23.3,39) v1(23.25,30.9) v1(23.45,47.6) v1(23.5,116.55) v1(23.79,90.4) v1(23.75,46.9) v1(23.7,44.2) v1(23.95,61.95) v1(24,41.4) v1(24,27) v1(24.1,39.9) v1(24.3,32.9) v1(24.3,29.3) v1(24.35,83.9) v1(24.45,34.45) v1(24.55,36.75) v1(24.6,38.2) v1(24.7,118.15) v1(24.75,47.85) v1(24.85,76.6) v1(24.85,47.1) v1(24.95,40.55) v1(25,68.45) v1(25,30.45) v1(25.15,87.7) v1(25.15,31.95) v1(25.25,28.05) v1(25.4,58.35) v1(25.39,48.4) v1(25.4,43.35) v1(25.39,42.2) v1(25.45,59.2) v1(25.59,112.75) v1(25.5,70.35) v1(25.55,47.7) v1(25.65,46.05) v1(25.65,35.2) v1(25.83,48.85) v1(25.85,38.95) v1(25.85,37.7) v1(25.85,36.45) v1(25.95,42.78) v1(26,41.62) v1(26.2,83.9) v1(26.1,72.3) v1(26.1,62.9) v1(26.1,44.2) v1(26.15,40.6) v1(26.1,39.6) v1(26.1,26.9) v1(26.45,59.7) v1(26.5,34.15) v1(26.5,30.25) v1(26.75,32.8) v1(26.9,35.3) v1(26.9,28.2) v1(27.05,31.6) v1(27.3,85.3) v1(27.35,67.1) v1(27.5,58.9) v1(27.55,41.2) v1(27.59,29.35) v1(27.6,43.2) v1(27.65,42.25) v1(27.75,79.8) v1(27.8,43.97) v1(27.8,40.33) v1(28,39.17) v1(28,38) v1(28,34.2) v1(28.05,32.45) v1(28,31) v1(28.05,29.95) v1(28.05,28.75) v1(28,27.7) v1(28,26.95) v1(28.2,87.45) v1(28.1,62.45) v1(28.29,84.1) v1(28.3,61.6) v1(28.35,112.45) v1(28.35,70.45) v1(28.4,42.9) v1(28.4,41.65) v1(28.35,36.9) v1(28.41,44.55) v1(28.41,39.8) v1(28.55,108.67) v1(28.5,40.6) v1(28.6,92.25) v1(28.75,118.45) v1(28.8,43.75) v1(28.9,74.75) v1(28.93,45.4) v1(29,61) v1(29,44.8) v1(29.1,46.35) v1(29.15,42.45) v1(29.2,38.7) v1(29.25,83.59) v1(29.25,37.65) v1(29.35,35.85) v1(29.45,40.8) v1(29.75,114.7) v1(29.7,62.75) v1(29.75,45.65) v1(29.75,44.4) v1(29.8,43.3) v1(29.9,68.95) v1(29.85,36.8) v1(29.95,67.6) v1(29.95,41.8) v1(30.05,39.95) v1(30.1,117.95) v1(30.2,102.3) v1(30.2,76.1) v1(30.1,35.1) v1(30.2,33.75) v1(30.15,31) v1(30.15,29.1) v1(30.15,27.8) v1(30.15,26.9) v1(30.3,100.4) v1(30.3,92.4) v1(30.31,72.9) v1(30.5,78.1) v1(30.5,42.5) v1(30.55,37.8) v1(30.65,95.2) v1(30.65,36.25) v1(30.77,93.5) v1(30.7,92.9) v1(30.8,41.4) v1(30.71,28.5) v1(30.95,74.5) v1(31,44.25) v1(31.05,39) v1(31.2,111) v1(31.15,46.25) v1(31.25,40.55) v1(31.3,32.95) v1(31.4,117.65) v1(31.35,35.6) v1(31.35,34.55) v1(31.45,72.1) v1(31.55,116.3) v1(31.65,102.45) v1(31.65,26.95) v1(31.75,30.75) v1(31.9,111.1) v1(32.05,39.7) v1(32.1,118.45) v1(32.1,97.25) v1(32.15,70.95) v1(32.15,37.8) v1(32.3,95.97) v1(32.25,41.7) v1(32.45,28.9) v1(32.5,34.15) v1(32.6,36.5) v1(32.8,114.65) v1(32.75,97.2) v1(32.83,115.5) v1(32.83,110.9) v1(32.9,39.05) v1(33.05,44.15) v1(33.1,88.55) v1(33.15,86.6) v1(33.2,85.5) v1(33.19,70.4) v1(33.3,74.1) v1(33.25,46.1) v1(33.3,32.95) v1(33.4,93.85) v1(33.4,93) v1(33.4,92.15) v1(33.35,55.9) v1(33.35,40.45) v1(33.55,64.3) v1(33.51,62.3) v1(33.59,59.1) v1(33.51,57.95) v1(33.5,35.35) v1(33.5,26.9) v1(33.75,65.25) v1(33.79,60.65) v1(33.75,41.75) v1(33.7,36.8) v1(33.8,30.55) v1(33.83,82.6) v1(33.87,72.25) v1(33.91,56.75) v1(33.95,38) v1(34.2,28) v1(34.35,111.15) v1(34.35,93.85) v1(34.35,93) v1(34.35,92.15) v1(34.5,34.3) v1(34.6,115.25) v1(34.67,63.95) v1(34.6,46.1) v1(34.79,118.55) v1(34.7,56.7) v1(34.75,40.35) v1(34.8,39.05) v1(34.8,36.55) v1(35.05,68.05) v1(35.19,62.15) v1(35.2,45.55) v1(35.15,41.75) v1(35.25,93.85) v1(35.25,93) v1(35.25,92.15) v1(35.27,56.15) v1(35.3,54.6) v1(35.3,42.8) v1(35.35,29.15) v1(35.4,27) v1(35.47,89.72) v1(35.5,32.95) v1(35.65,53.95) v1(35.8,48.85) v1(35.75,37.45) v1(35.8,35.45) v1(35.85,49.4) v1(35.99,95.2) v1(35.95,94.75) v1(35.95,74.55) v1(35.99,63.6) v1(36,72.95) v1(36.07,65.3) v1(36.03,60.7) v1(36.05,44.75) v1(36.25,113.3) v1(36.25,40.35) v1(36.5,55.45) v1(36.5,43.35) v1(36.7,109.65) v1(36.79,59.1) v1(36.71,57.6) v1(36.79,54.15) v1(36.7,46.3) v1(36.7,41.85) v1(36.7,30.65) v1(36.9,36.6) v1(36.85,34.4) v1(36.95,98.57) v1(36.95,39.05) v1(37.2,115.3) v1(37.3,45.2) v1(37.25,28) v1(37.4,95.95) v1(37.59,62.15) v1(37.79,64.25) v1(37.79,49.05) v1(37.9,37.7) v1(37.9,35.6) v1(38,32.95) v1(38.11,55.35) v1(38.15,43.35) v1(38.15,41.55) v1(38.15,29.3) v1(38.27,78.35) v1(38.23,57.2) v1(38.35,60.55) v1(38.35,46.15) v1(38.55,27.05) v1(38.6,39.6) v1(38.7,115.3) v1(38.85,34.65) v1(38.95,86.9) v1(39.03,63.5) v1(39.05,36.7) v1(39.15,42.55) v1(39.23,59) v1(39.25,44.75) v1(39.25,30.7) v1(39.35,109.25) v1(39.31,49.35) v1(39.45,83.6) v1(39.5,95.25) v1(39.55,54.7) v1(39.8,46.3) v1(39.7,40.9) v1(39.9,95.7) v1(39.9,39.1) v1(40.05,86.75) v1(40.05,75.4) v1(40.07,62.2) v1(40.03,60.55) v1(40.1,99.5) v1(40.1,97.3) v1(40.15,43.2) v1(40.35,96.05) v1(40.4,36.05) v1(40.43,56.1) v1(40.63,58.05) v1(40.65,32.9) v1(40.7,37.65) v1(40.83,65.35) v1(40.99,63.9) v1(41,69.5) v1(41.03,49.05) v1(41,27.4) v1(41.2,93.5) v1(41.23,45.8) v1(41.25,44.45) v1(41.32,73.7) v1(41.55,80.4) v1(41.65,30.45) v1(42.15,95.65) v1(42.2,55) v1(42.25,99.25) v1(42.23,46.25) v1(42.3,28.8) v1(42.39,63.5) v1(42.39,62.15) v1(42.39,60.45) v1(42.35,59.1) v1(42.31,57.15) v1(42.45,83.2) v1(42.43,64.8) v1(42.55,85.7) v1(42.55,74) v1(43,105.5) v1(43,34.6) v1(43,27.05) v1(43.25,75.9) v1(43.3,36.6) v1(43.25,30.2) v1(43.35,46.9) v1(43.35,41.95) v1(43.55,33.4) v1(43.69,99) v1(43.75,86.2) v1(43.85,92.75) v1(44.35,45.1) v1(44.45,42) v1(44.79,48.55) v1(44.79,47.05) v1(44.7,32) v1(44.9,101.25) v1(45.05,107.45) v1(45,85.55) v1(45.15,74.8) v1(45.11,69.25) v1(45.23,104.8) v1(45.4,96.25) v1(45.39,45.5) v1(45.45,94.8) v1(45.6,31) v1(45.75,27.05) v1(45.85,103.9) v1(45.85,36.3) v1(46.07,111.15) v1(46.19,48.75) v1(46.2,39.5) v1(46.39,47.2) v1(46.55,104.8) v1(46.5,92.8) v1(46.55,50.25) v1(46.59,44.8) v1(46.67,42.35) v1(46.7,37.6) v1(47.05,106) v1(47,87.15) v1(47.3,115.1) v1(47.3,82.55) v1(47.25,79.75) v1(47.25,73.5) v1(47.35,102.4) v1(47.35,95.55) v1(47.4,70.9) v1(47.35,33.35) v1(47.51,92.1) v1(47.5,35.75) v1(47.65,30.5) v1(47.8,90.95) v1(47.71,46.1) v1(47.75,40.75) v1(47.95,77.9) v1(47.95,28.3) v1(48,69.15) v1(48.15,103) v1(48.15,44.05) v1(48.27,42.35) v1(48.45,99.55) v1(48.55,105.9) v1(48.55,59.25) v1(48.8,39.5) v1(48.85,85.15) v1(48.85,73.5) v1(49,102.2) v1(49.18,101.62) v1(49.2,34.05) v1(49.4,31.75) v1(49.45,102.95) v1(49.55,71.15) v1(49.55,37.55) v1(49.63,42) v1(49.65,28.95) v1(49.95,92.9) v1(50.15,75.9) v1(50.15,40.85) v1(50.25,100.4) v1(50.39,43.75) v1(50.8,64.55) v1(50.85,67) v1(50.95,59.9) v1(51.05,72.15) v1(51.3,27.05) v1(51.4,85.5) v1(51.65,82.1) v1(51.65,74.15) v1(51.7,32.85) v1(51.9,114.65) v1(51.9,42.55) v1(51.91,117.61) v1(52.1,70.75) v1(52.15,43.6) v1(52.4,30.6) v1(52.5,87.45) v1(52.67,117.65) v1(52.8,95.7) v1(52.72,95.07) v1(52.75,75.8) v1(53.15,109.7) v1(53.15,91.15) v1(53.1,79.95) v1(53.15,27.5) v1(53.25,102.85) v1(53.25,74.6) v1(54.05,28.85) v1(54.3,53.05) v1(54.3,49.9) v1(54.35,56.85) v1(54.35,44) v1(54.45,33.95) v1(54.5,39.5) v1(54.7,81.45) v1(54.7,61.5) v1(54.85,65.55) v1(55.05,31.9) v1(55.2,102.65) v1(55.1,84.1) v1(55.1,46.55) v1(55.15,35.5) v1(55.22,99.9) v1(55.71,72.7) v1(55.75,43.35) v1(55.7,29.1) v1(56.03,79.75) v1(56.2,27.05) v1(56.55,92) v1(56.5,84.1) v1(56.6,62.3) v1(56.6,40.1) v1(56.85,94.35) v1(56.85,58.2) v1(56.85,35.5) v1(56.95,81.8) v1(56.95,53.1) v1(57.1,103) v1(57.2,113.45) v1(57.15,95.95) v1(57.3,106.75) v1(57.35,104.35) v1(57.39,89.9) v1(57.3,42.15) v1(57.35,37.15) v1(57.4,28.65) v1(57.45,64.25) v1(57.45,60.25) v1(57.45,56.25) v1(57.45,50.25) v1(57.45,46.3) v1(57.45,32.95) v1(57.55,69.5) v1(57.5,67.35) v2(27.38,54.15) v2(27.38,53.15) v2(27.38,52.15) v2(27.38,51.15) v2(27.38,50.15) v2(28.38,54.15) v2(28.38,53.15) v2(28.38,52.15) v2(28.38,51.15) v2(28.38,50.15) v2(29.38,54.15) v2(29.38,53.15) v2(29.38,52.15) v2(29.38,51.15) v2(29.38,50.15) v2(30.38,54.15) v2(30.38,53.15) v2(30.38,52.15) v2(30.38,51.15) v2(30.38,50.15) v2(31.38,54.15) v2(31.38,53.15) v2(31.38,52.15) v2(31.38,51.15) v2(31.38,50.15)
